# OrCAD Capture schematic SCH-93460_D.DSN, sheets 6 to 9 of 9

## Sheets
6 05. LED, MEMORY, XTAL: size C
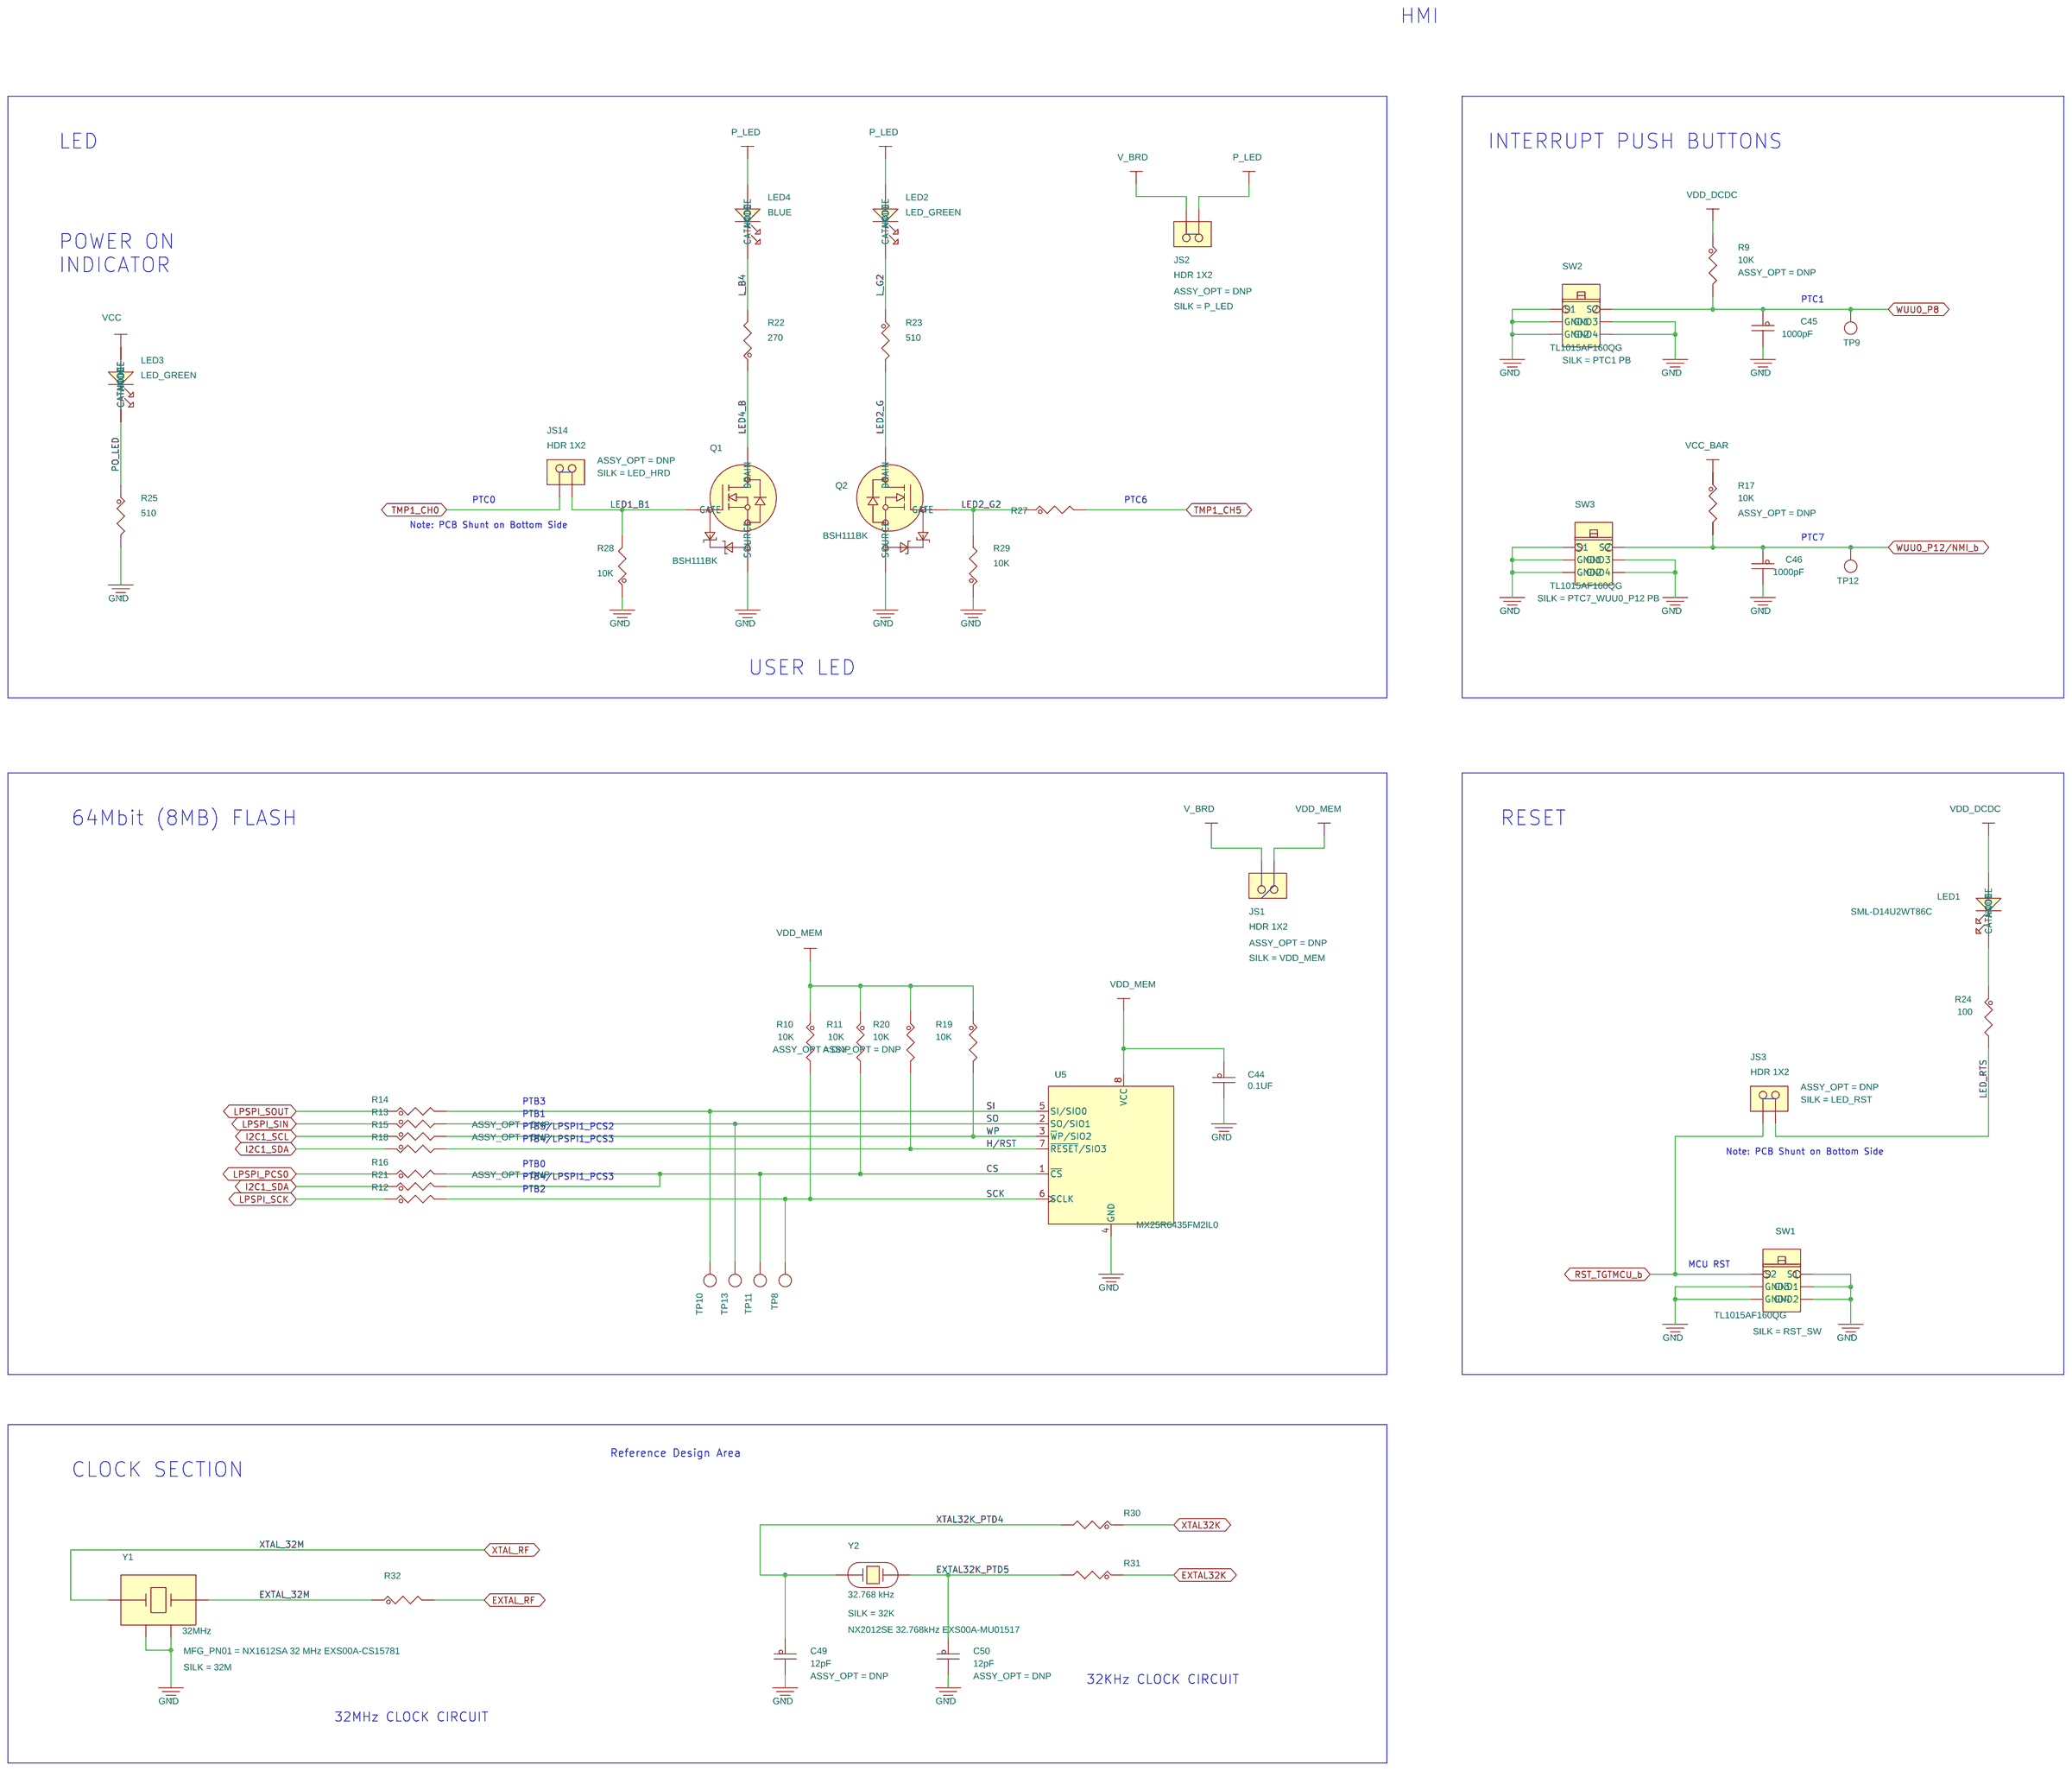
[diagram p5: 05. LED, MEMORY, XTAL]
7 06. MCU Link: size C
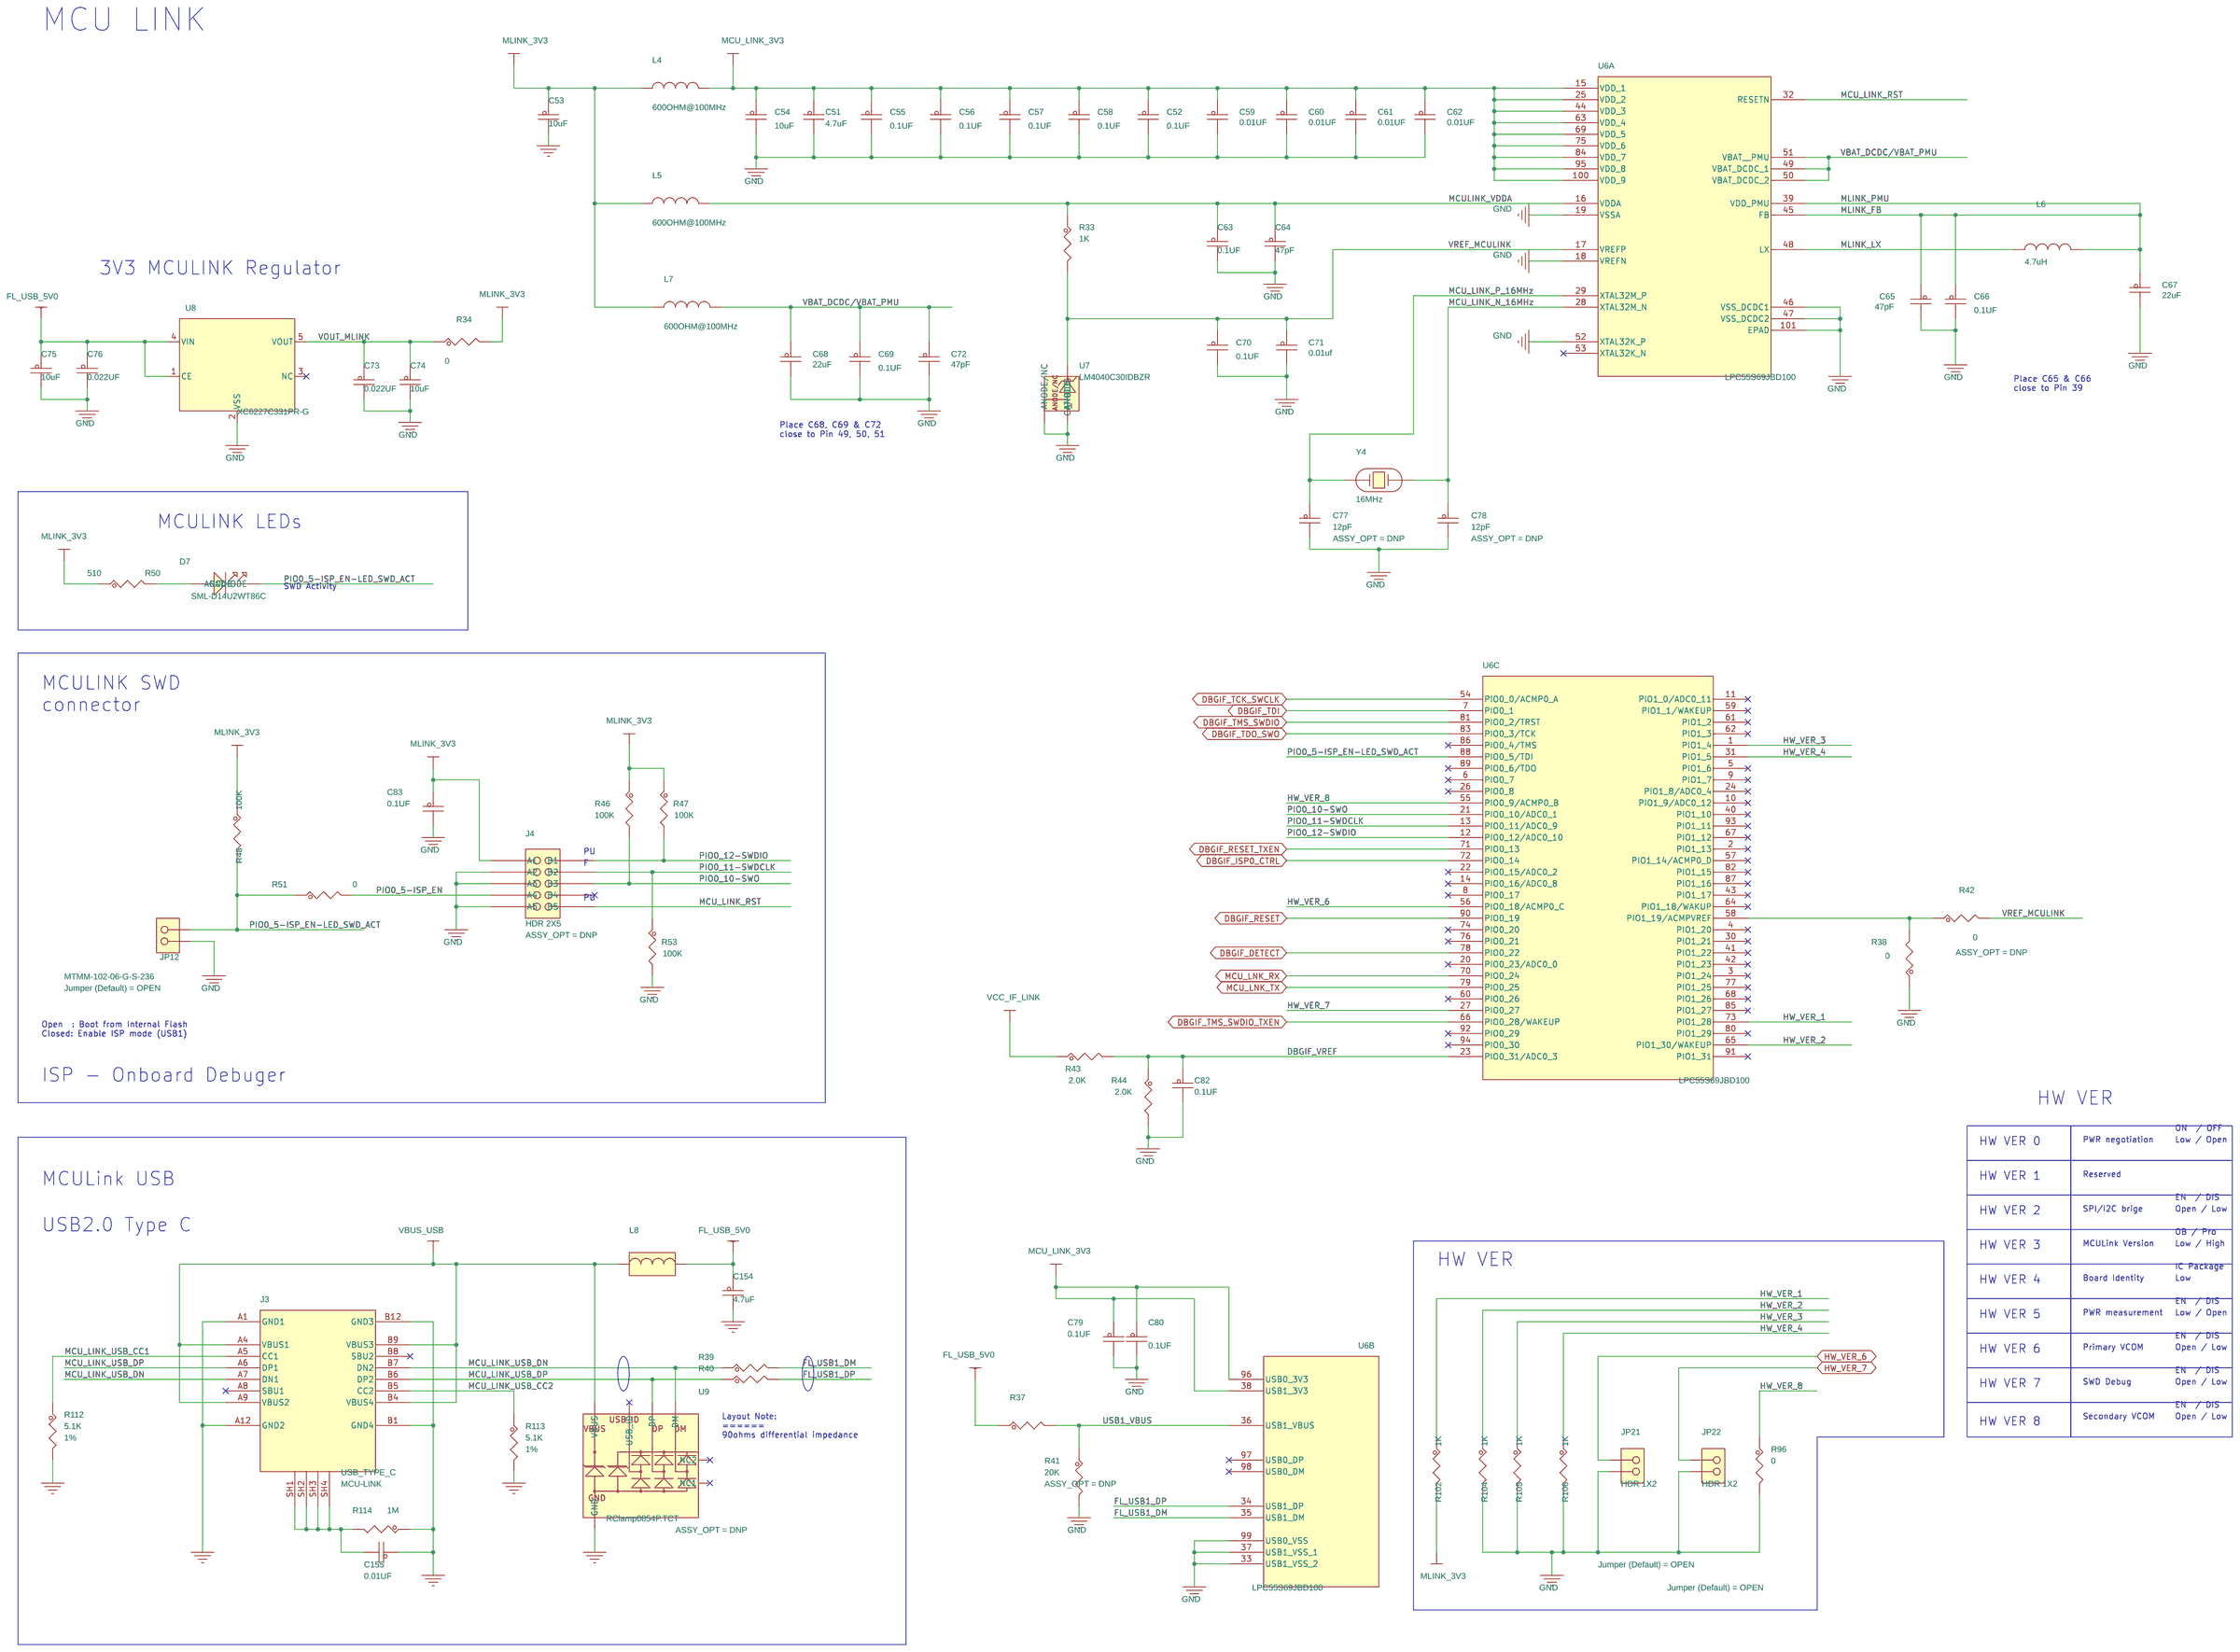
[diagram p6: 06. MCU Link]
8 07. MCU Link SWD: size C
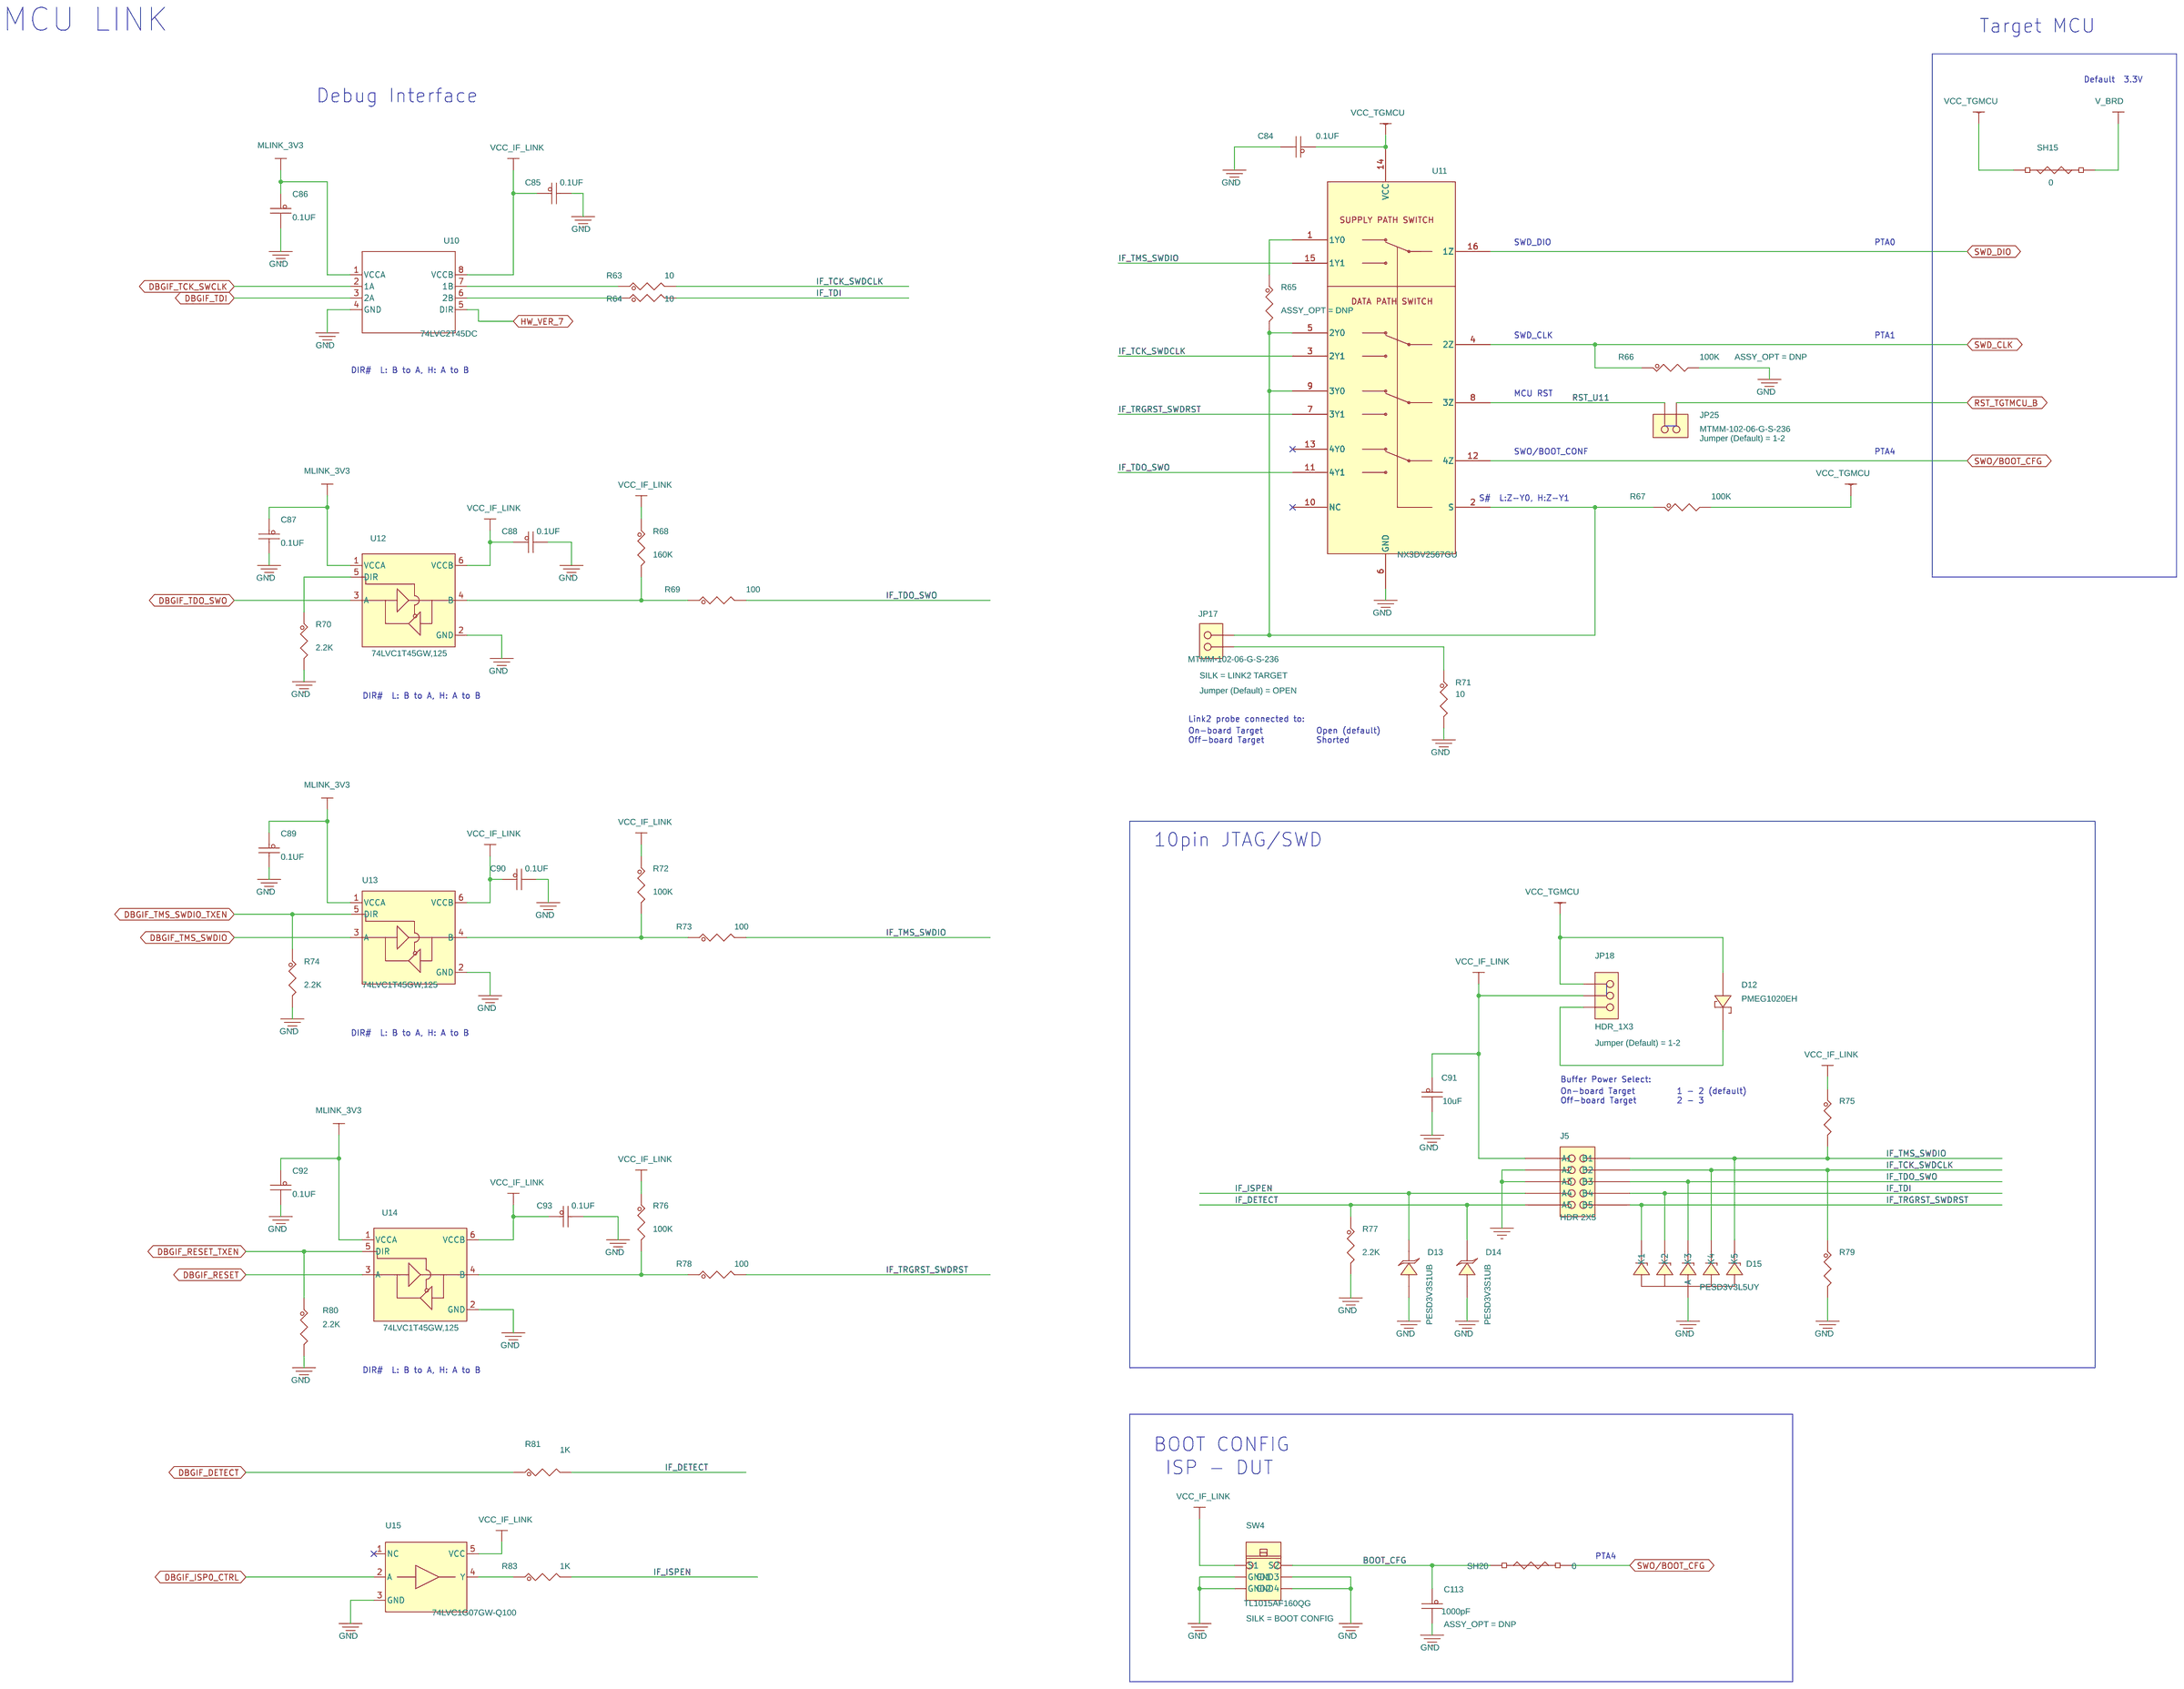
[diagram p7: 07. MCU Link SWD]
9 08. MLink IO, MikroBus: size C
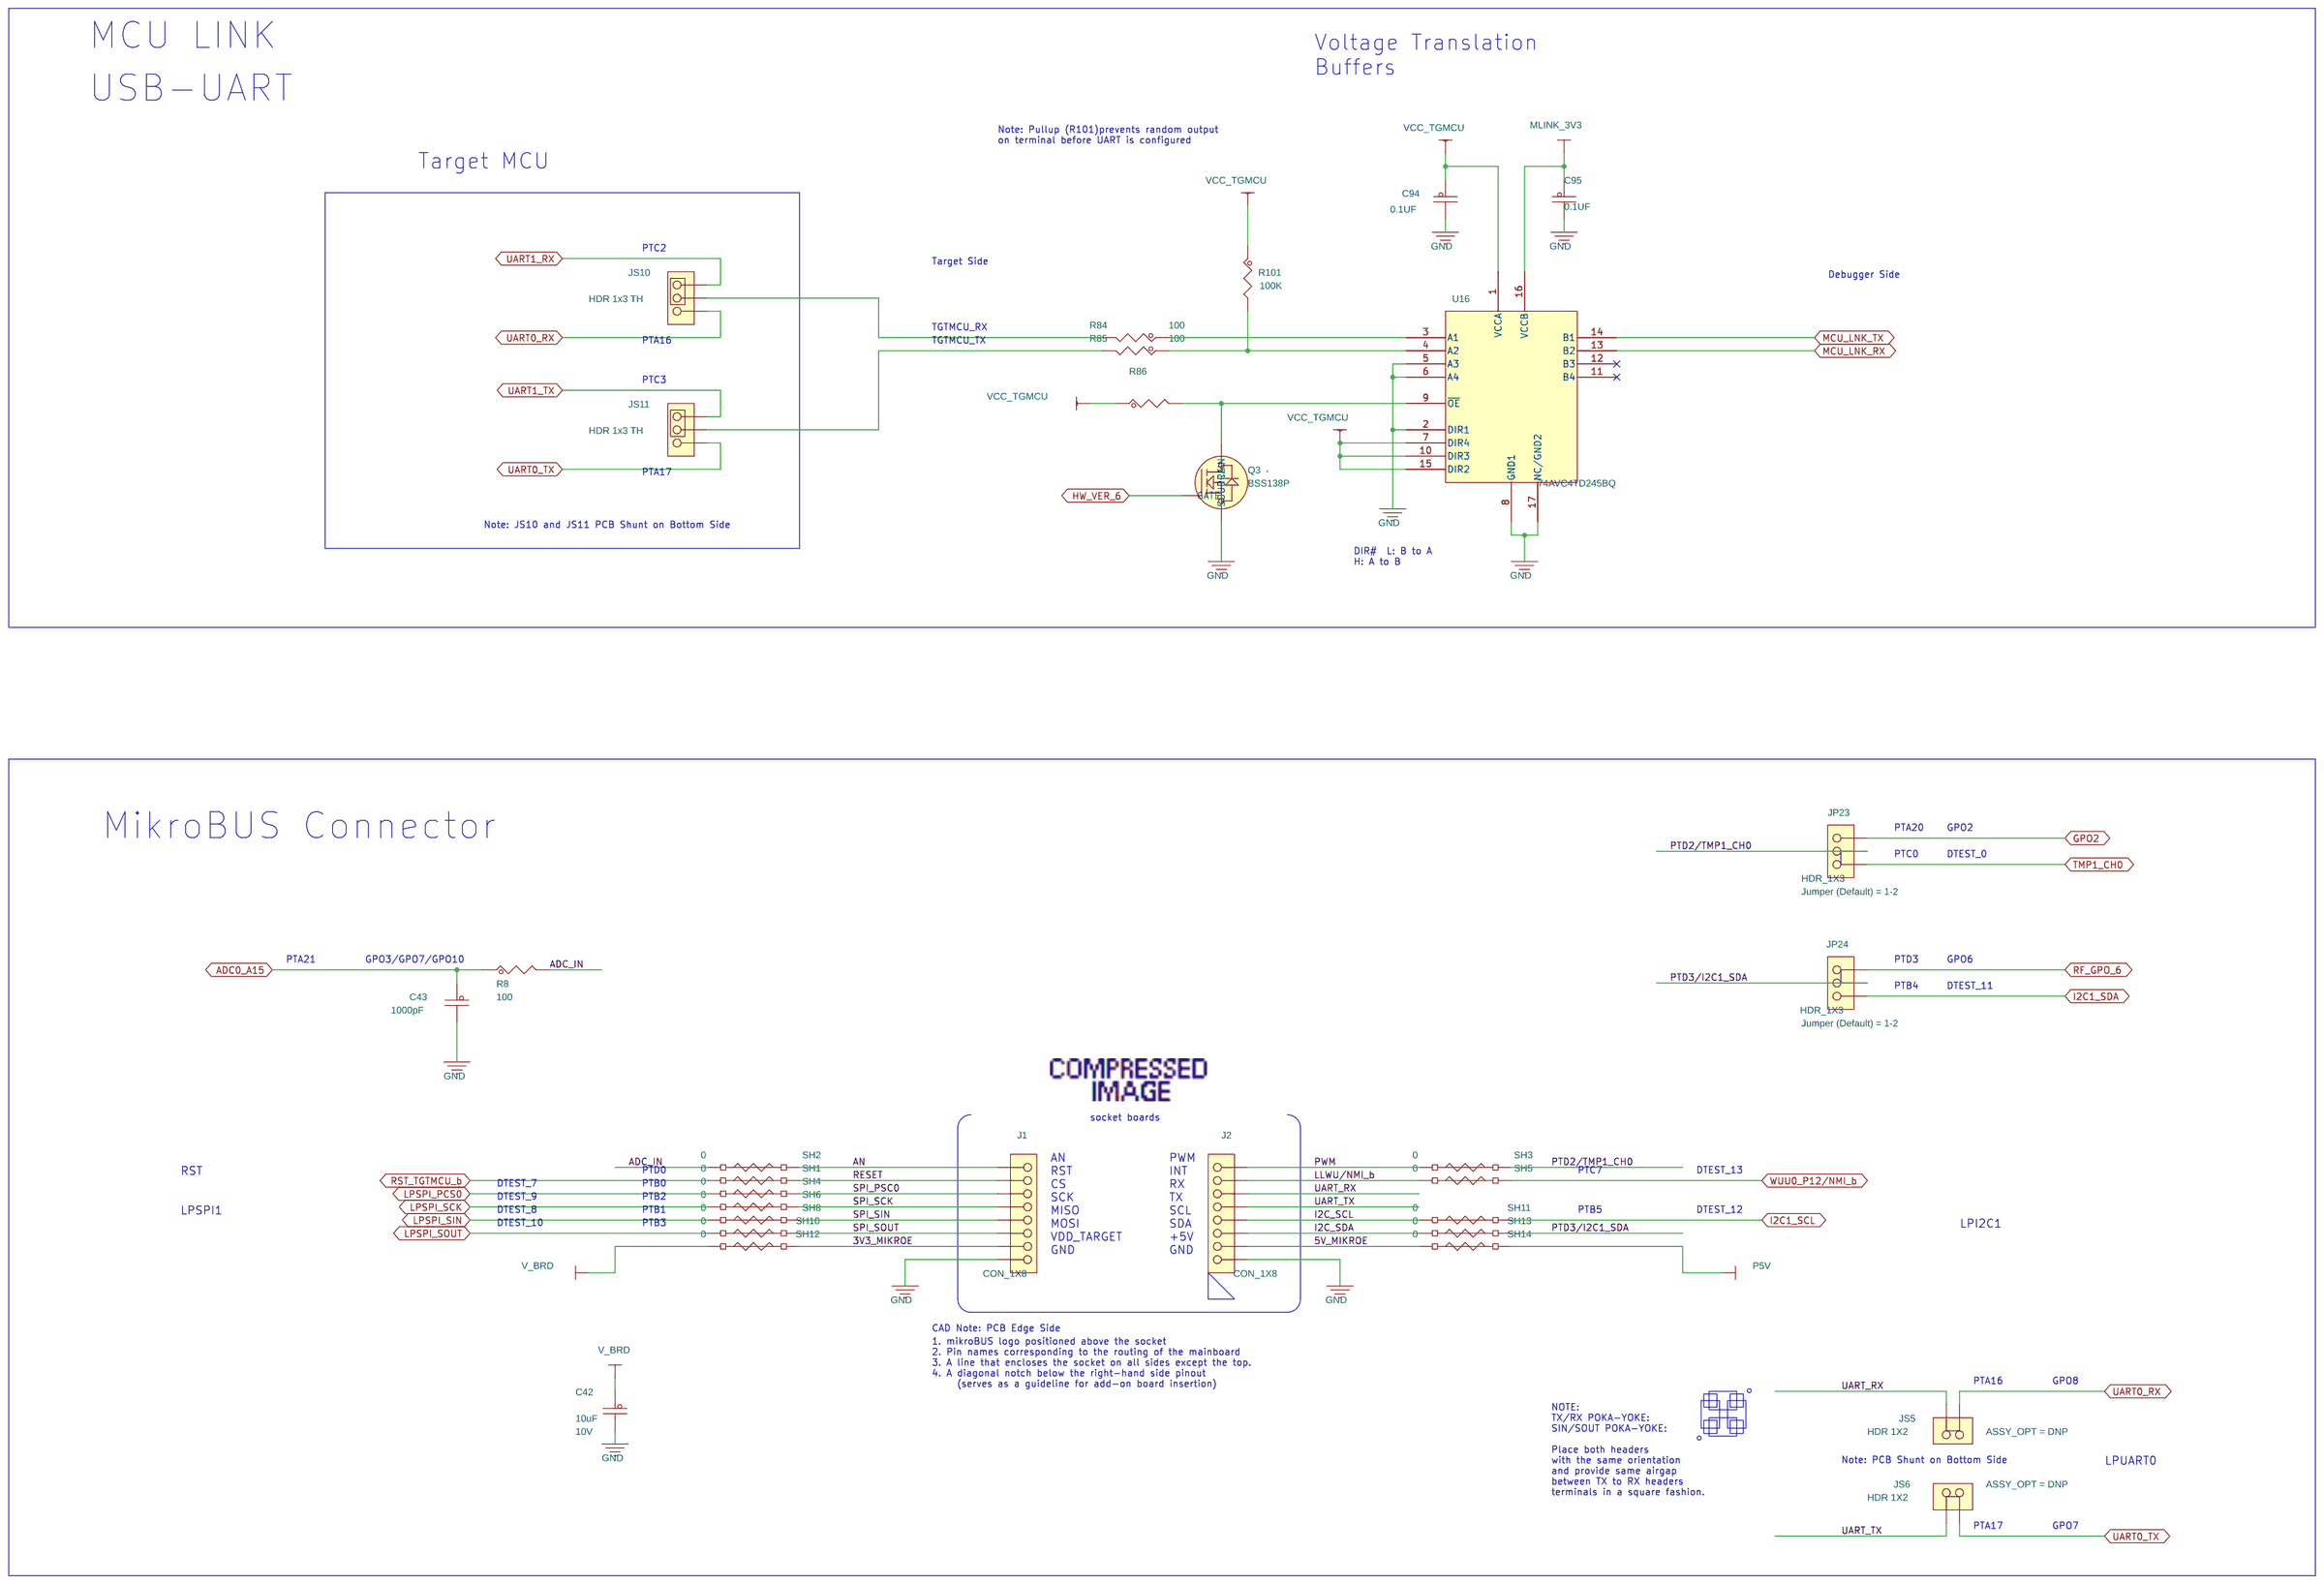
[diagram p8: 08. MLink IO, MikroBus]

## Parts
sheet 05. LED, MEMORY, XTAL
C44  0.1UF  [CC0402_25]
C45  1000pF  [CC0402_25]
C46  1000pF  [CC0402_25]
C49  12pF  [CC0402_25]
C50  12pF  [CC0402_25]
JS1  HDR 1X2  [sh_hdr102_2mm_bottom]
JS2  HDR 1X2  [sh_hdr102_2mm_bottom]
JS3  HDR 1X2  [sh_hdr102_2mm_bottom]
JS14  HDR 1X2  [sh_hdr102_2mm_bottom]
LED1  SML-D14U2WT86C  [led_0603]
LED2  LED_GREEN  [LED_0603]
LED3  LED_GREEN  [LED_0603]
LED4  BLUE  [led2_2p34_2p1x1p25]
Q1  BSH111BK  [SOT23_A]
Q2  BSH111BK  [SOT23_A]
R9  10K  [RC0402_25]
R10  10K  [RC0402_25]
R11  10K  [RC0402_25]
R12  0  [RC0402_25]
R13  0  [RC0402_25]
R14  0  [RC0402_25]
R15  0  [RC0402_25]
R16  0  [RC0402_25]
R17  10K  [RC0402_25]
R18  0  [RC0402_25]
R19  10K  [RC0402_25]
R20  10K  [RC0402_25]
R21  0  [RC0402_25]
R22  270  [RC0402_25]
R23  510  [RC0402_25]
R24  100  [RC0402_25]
R25  510  [RC0402_25]
R27  0  [RC0402_25]
R28  10K  [RC0402_25]
R29  10K  [RC0402_25]
R30  0  [RC0402_25]
R31  0  [RC0402_25]
R32  0  [RC0402_25]
SW1  TL1015AF160QG  [sw2_spst_4x3_sm]
SW2  TL1015AF160QG  [sw2_spst_4x3_sm]
SW3  TL1015AF160QG  [sw2_spst_4x3_sm]
TP8  TPAD_030  [TPAD_030]
TP9  TPAD_030  [TPAD_030]
TP10  TPAD_030  [TPAD_030]
TP11  TPAD_030  [TPAD_030]
TP12  TPAD_030  [TPAD_030]
TP13  TPAD_030  [TPAD_030]
U5  MX25R6435FM2IL0  [SO8_W]
Y1  32MHz  [xtal4_1p6x1p2]
Y2  32.768 kHz  [xtal2_2x1p2_sm]
sheet 06. MCU Link
C51  4.7uF  [CC0603_OV]
C52  0.1UF  [CC0402_25]
C53  10uF  [CC0805_OV]
C54  10uF  [CC0805_OV]
C55  0.1UF  [CC0402_25]
C56  0.1UF  [CC0402_25]
C57  0.1UF  [CC0402_25]
C58  0.1UF  [CC0402_25]
C59  0.01UF  [CC0402_25]
C60  0.01UF  [CC0402_25]
C61  0.01UF  [CC0402_25]
C62  0.01UF  [CC0402_25]
C63  0.1UF  [CC0402_25]
C64  47pF  [CC0603_OV]
C65  47pF  [CC0603_OV]
C66  0.1UF  [CC0402_25]
C67  22uF  [CC0603_OV]
C68  22uF  [CC0603_OV]
C69  0.1UF  [CC0402_25]
C70  0.1UF  [CC0402_25]
C71  0.01uf  [CC0603_OV]
C72  47pF  [CC0603_OV]
C73  0.022UF  [CC0603_OV]
C74  10uF  [CC0805_OV]
C75  10uF  [CC0805_OV]
C76  0.022UF  [CC0603_OV]
C77  12pF  [CC0402_25]
C78  12pF  [CC0402_25]
C79  0.1UF  [CC0402_25]
C80  0.1UF  [CC0402_25]
C82  0.1UF  [CC0402_25]
C83  0.1UF  [CC0402_25]
C154  4.7uF  [CC0603_OV]
C155  0.01UF  [CC0805_OV]
D7  SML-D14U2WT86C  [led_0603]
J3  USB_TYPE_C  [con16_usb_type-c_ra_th]
J4  HDR 2X5  [con2x5_50_th_a]
JP12  MTMM-102-06-G-S-236  [hdr102_tmm]
JP21  HDR 1X2  [hdr102_338h]
JP22  HDR 1X2  [hdr102_338h]
L4  600OHM@100MHz  [ind_1p8x1mm_sm]
L5  600OHM@100MHz  [ind_1p8x1mm_sm]
L6  4.7uH  [ind_5p2x5p2]
L7  600OHM@100MHz  [ind_1p8x1mm_sm]
L8  330 OHM  [ind_1608]
R33  1K  [RC0402_25]
R34  0  [RC0603_OV]
R37  10K  [RC0603_OV]
R38  0  [RC0603_OV]
R39  0  [RC0402_25]
R40  0  [RC0402_25]
R41  20K  [RC0402_25]
R42  0  [RC0603_OV]
R43  2.0K  [RC0603_OV]
R44  2.0K  [RC0603_OV]
R46  100K  [RC0402_25]
R47  100K  [RC0402_25]
R48  100K  [RC0402_25]
R50  510  [RC0402_25]
R51  0  [RC0603_OV]
R53  100K  [RC0402_25]
R96  0  [RC0603_OV]
R102  1K  [RC0402_25]
R104  1K  [RC0402_25]
R105  1K  [RC0402_25]
R106  1K  [RC0402_25]
R112  5.1K  [RC0402_25]
R113  5.1K  [RC0402_25]
R114  1M  [RC0805_OV]
U6  LPC55S69JBD100  [hlqfp100_0p5_14x14]  (sections A,B,C)
U7  LM4040C30IDBZR  [SOT23-3]
U8  XC6227C331PR-G  [SOT89-5]
U9  RClamp0854P.TCT  [slp1616p6]
Y4  16MHz  [xtal2_3p3x2p6]
sheet 07. MCU Link SWD
C84  0.1UF  [CC0402_25]
C85  0.1UF  [CC0402_25]
C86  0.1UF  [CC0402_25]
C87  0.1UF  [CC0402_25]
C88  0.1UF  [CC0402_25]
C89  0.1UF  [CC0402_25]
C90  0.1UF  [CC0402_25]
C91  10uF  [cc0402_tol0p2]
C92  0.1UF  [CC0402_25]
C93  0.1UF  [CC0402_25]
C113  1000pF  [CC0402_25]
D12  PMEG1020EH  [SOD123LF]
D13  PESD3V3S1UB  [sod523]
D14  PESD3V3S1UB  [sod523]
D15  PESD3V3L5UY  [sot-363_0p65_smt]
J5  HDR 2X5  [con2x5_50_th_a]
JP17  MTMM-102-06-G-S-236  [hdr102_tmm]
JP18  HDR_1X3  [hdr103_78mil]
JP25  MTMM-102-06-G-S-236  [hdr102_tmm]
R63  10  [RC0402_25]
R64  10  [RC0402_25]
R65  0  [RC0402_25]
R66  100K  [RC0402_25]
R67  100K  [RC0402_25]
R68  160K  [RC0402_25]
R69  100  [RC0402_25]
R70  2.2K  [RC0402_25]
R71  10  [RC0402_25]
R72  100K  [RC0402_25]
R73  100  [RC0402_25]
R74  2.2K  [RC0402_25]
R75  10K  [RC0402_25]
R76  100K  [RC0402_25]
R77  2.2K  [RC0402_25]
R78  100  [RC0402_25]
R79  10K  [RC0402_25]
R80  2.2K  [RC0402_25]
R81  1K  [RC0402_25]
R83  1K  [RC0402_25]
SH15  0  [SH0402]
SH20  0  [SH0603]
SW4  TL1015AF160QG  [sw2_spst_4x3_sm]
U10  74LVC2T45DC  [SSOP8_DCU]
U11  NX3DV2567GU  [pqfn16_0p4_2p65x1p85]
U12  74LVC1T45GW,125  [SOT-363_0P65_SMT]
U13  74LVC1T45GW,125  [SOT-363_0P65_SMT]
U14  74LVC1T45GW,125  [SOT-363_0P65_SMT]
U15  74LVC1G07GW-Q100  [sc70-5]
sheet 08. MLink IO, MikroBus
C42  10uF  [cc0402_tol0p2]
C43  1000pF  [CC0402_25]
C94  0.1UF  [CC0402_25]
C95  0.1UF  [CC0402_25]
J1  CON_1X8  [con_1x8_skt_2p54_th]
J2  CON_1X8  [con_1x8_skt_2p54_th]
JP23  HDR_1X3  [hdr103_78mil]
JP24  HDR_1X3  [hdr103_78mil]
JS5  HDR 1X2  [sh_hdr102_tmm_bottom]
JS6  HDR 1X2  [sh_hdr102_tmm_bottom]
JS10  HDR 1x3 TH  [hdr103_short1_2]
JS11  HDR 1x3 TH  [hdr103_short1_2]
Q3  BSS138P  [sot23_a]
R8  100  [RC0402_25]
R84  100  [RC0402_25]
R85  100  [RC0402_25]
R86  10K  [RC0402_25]
R101  100K  [RC0402_25]
SH1  0  [SH0402]
SH2  0  [SH0402]
SH3  0  [SH0402]
SH4  0  [SH0402]
SH5  0  [SH0402]
SH6  0  [SH0402]
SH8  0  [SH0402]
SH10  0  [SH0402]
SH11  0  [SH0402]
SH12  0  [SH0402]
SH13  0  [SH0402]
SH14  0  [SH0402]
U16  74AVC4TD245BQ  [dhvqfn16_0p5_3p6x2p6]

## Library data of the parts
C44 C52 C55-C58 C63 C66 C69 C70 C79 C80 C82 = CAP_NP: CAP CER 0.1UF 16V 10% X7R 0402; 3D_Mechanical_Footprint_File: http://fcl.am.freescale.net/ALLEGRO/step/cc0402_25.STEP; AGILE_PN: 150-75182; CAD_APPROVED: Yes; FPLIST: CC0402_25,CC0402_HD,0402_CC,CAPC0402_L; HEIGHT: 0.635mm; MFG_NAME01: KEMET; MFG_PN01: C0402C104K4RACTU; ROHS: NULL; Rated Voltage: 16V; Temp Range: -55C to +125C; Tolerance: 10%; VOLTAGE: 16V
C43 C45 C46 = CAP_NP: CAP CER 1000PF 50V 5% C0G 0402; AGILE_PN: 150-76334; CAD_APPROVED: Yes; FPLIST: CC0402_25,CC0402_HD,0402_CC; HEIGHT: 0.55mm; MFG_NAME01: GUANGDONG VIIYONG ELECTRONIC TECHNOLOGYCO., LTD.VIIYONG; MFG_PN01: V102J0402C0G500NBT; Package Size: 0402; Package Type: 180mm Paper Tape; ROHS: NULL; Rated Voltage: 50V; Temp Range: -55C to +125C; Tolerance: 5%; VOLTAGE: 50V
C49 C50 C77 C78 = CAP_NP: CAP CER 12pF 50V 5% C0G AEC-Q200 0402; AGILE_PN: 150-80457; ASSY_OPT: DNP; CAD_APPROVED: Yes; FPLIST: CC0402_25,CC0402_HD,0402_CC,capc0402_l; HEIGHT: 0.55MM; MFG_NAME01: MURATA; MFG_PN01: GCM1555C1H120JA16D; Package Size: 0402; ROHS: NULL; Rated Voltage: 50V; Temp Range: -55C to +125C; Tolerance: 5%; VOLTAGE: 50V
JS1 = CONN_HDR_2X1: HDR 1X2 TH 2MM SP 217H AU 110L, NO PART TO ORDER; AGILE_PN: 210-80699; ASSY_OPT: DNP; CAD_APPROVED: Yes; FPLIST: sh_hdr102_2mm_bottom,sh_hdr102_2mm_bottom_a; HEIGHT: 5.2; MFG_PN01: NO_PART_TO_ORDER; ROHS: Yes; SHORTED (DEFAULT): CLOSED; SILK: VDD_MEM; Temp_Range: -55°C to +125°C
JS2 = CONN_HDR_2X1: HDR 1X2 TH 2MM SP 217H AU 110L, NO PART TO ORDER; AGILE_PN: 210-80699; ASSY_OPT: DNP; CAD_APPROVED: Yes; FPLIST: sh_hdr102_2mm_bottom,sh_hdr102_2mm_bottom_a; HEIGHT: 5.2; MFG_PN01: NO_PART_TO_ORDER; ROHS: Yes; SHORTED (DEFAULT): CLOSED; SILK: P_LED; Temp_Range: -55°C to +125°C
JS3 = CONN_HDR_2X1: HDR 1X2 TH 2MM SP 217H AU 110L, NO PART TO ORDER; AGILE_PN: 210-80699; ASSY_OPT: DNP; CAD_APPROVED: Yes; FPLIST: sh_hdr102_2mm_bottom,sh_hdr102_2mm_bottom_a; HEIGHT: 5.2; MFG_PN01: NO_PART_TO_ORDER; ROHS: Yes; SHORTED (DEFAULT): CLOSED; SILK: LED_RST; Temp_Range: -55°C to +125°C
JS14 = CONN_HDR_2X1: HDR 1X2 TH 2MM SP 217H AU 110L, NO PART TO ORDER; AGILE_PN: 210-80699; ASSY_OPT: DNP; CAD_APPROVED: Yes; FPLIST: sh_hdr102_2mm_bottom,sh_hdr102_2mm_bottom_a; HEIGHT: 5.2; MFG_PN01: NO_PART_TO_ORDER; ROHS: Yes; SHORTED (DEFAULT): CLOSED; SILK: LED_HRD; Temp_Range: -55°C to +125°C
D7 LED1 = LED: LED RED SGL 20mA 2V AEC-Q101 0603; AGILE_PN: 370-76847; CAD_APPROVED: Yes; HEIGHT: 0.55; MFG_NAME01: ROHM; Package Size: 0603 (1608 Metric); Rated Voltage: 2V; Temp Range: -40C to +100C; VOLTAGE: 2V
LED2 LED3 = LED: LED ULTRA-BRIGHT GREEN SMT 0603; AGILE_PN: 370-75077; CAD_APPROVED: YES; HEIGHT: 0.8; MFG_NAME01: LITE ON; MFG_PN01: LTST-C190KGKT; ROHS: Yes; Rated Voltage: 2V; VOLTAGE: 2V
LED4 = LED: LED BLUE SGL 20MA SMT 0805; 3D_Mechanical_Footprint_File: http://fcl.am.freescale.net/ALLEGRO/step/led2_2p34_2p1x1p25.step; AGILE_PN: 370-76451; CAD_APPROVED: Yes; HEIGHT: 0.9; MFG_NAME01: LITE ON; MFG_PN01: LTST-C171TBKT; Rated Voltage: 2.8V; Temp Range: -20° C to +80° C; VOLTAGE: 2.8V
Q1 Q2 = NMOS_2N7002BKW_3P: TRAN NMOS SW FET 55V 210mA SOT23; AGILE_PN: 480-79704; CAD_APPROVED: Yes; HEIGHT: 1.1; MFG_NAME01: NEXPERIA; MFG_PN01: BSH111BKR; ROHS: Yes
R9 R11 R17 = RES: RES MF 10K 1/16W 1% 0402; AGILE_PN: 470-80452; ASSY_OPT: DNP; CAD_APPROVED: Yes; FPLIST: RC0402_25,RC0402_HD,0402_CC; HEIGHT: 0.40; MFG_NAME01: VISHAY; MFG_PN01: CRCW040210K0FKEDC; PRIORITY_PN: 006-00552; ROHS: Yes; TOL: 1%; Tolerance: 1%
R10 = RES: RES MF 10K 1/16W 1% 0402; AGILE_PN: 470-80452; ASSY_OPT: DNP; CAD_APPROVED: Yes; FPLIST: RC0402_25,RC0402_HD,0402_CC; HEIGHT: 0.40; MFG_NAME01: VISHAY; MFG_PN01: CRCW040210K0FKEDC; ROHS: Yes; Tolerance: 1%
R12-R14 R16 R27 R30-R32 R39 R40 = RES: RES MF ZERO OHM 1/16W 5% 0402; AGILE_PN: 470-75394; CAD_APPROVED: Yes; FPLIST: RC0402_25,RC0402_HD,RC0402_X2,0402_CC; HEIGHT: 0.45; MFG_NAME01: YAGEO AMERICA; MFG_PN01: RC0402JR-070RL; ROHS: Yes; Temp Range: -55 to +155C; Tolerance: 5%; VOLTAGE: 1/16W
R15 R18 R21 R65 = RES: RES MF ZERO OHM 1/16W 5% 0402; AGILE_PN: 470-75394; ASSY_OPT: DNP; CAD_APPROVED: Yes; FPLIST: RC0402_25,RC0402_HD,RC0402_X2,0402_CC; HEIGHT: 0.45; MFG_NAME01: YAGEO AMERICA; MFG_PN01: RC0402JR-070RL; ROHS: Yes; Temp Range: -55 to +155C; Tolerance: 5%; VOLTAGE: 1/16W
R19 R20 R28 R29 = RES: RES MF 10K 1/16W 1% 0402; AGILE_PN: 470-80452; CAD_APPROVED: Yes; FPLIST: RC0402_25,RC0402_HD,0402_CC; HEIGHT: 0.40; MFG_NAME01: VISHAY; MFG_PN01: CRCW040210K0FKEDC; ROHS: Yes; Tolerance: 1%
R22 = RES: RES MF 270 OHM 1/16W 1% AEC-Q200 0402; 3D_Mechanical_Footprint_File: http://fcl.am.freescale.net/ALLEGRO/step/rc0402_25.STEP; AGILE_PN: 470-83516; CAD_APPROVED: Yes; FPLIST: RC0402_25,RC0402_HD,0402_CC; HEIGHT: 0.37; MFG_NAME01: YAGEO AMERICA; MFG_PN01: AC0402FR-07270RL; Package Size: 0402 (1005 Metric); ROHS: Yes; Temp Range: -55C to +155C; Tolerance: 1%
R23 R25 = RES: RES 510 OHMS 1/16W 5% RC0402 ROHS; AGILE_PN: 470-76237; CAD_APPROVED: Yes; FPLIST: RC0402_25,RC0402_HD,0402_CC; HEIGHT: 0.4; MFG_NAME01: YAGEO AMERICA; MFG_PN01: RC0402JR-07510RL; ROHS: Yes
R8 R24 R69 R73 R78 R84 R85 = RES: RES MF 100 OHM 1/16W 5% 0402; AGILE_PN: 470-75591; CAD_APPROVED: Yes; FPLIST: RC0402_25,RC0402_HD,RC0402_X2,0402_CC; HEIGHT: 0.45; MFG_NAME01: BOURNS; MFG_PN01: CR0402-JW-101GLF; ROHS: Yes; Tolerance: 5%
SW1 = SW_SPNO_2P_GND6P: SW SPST PB 50MA 12V SMT; AGILE_PN: 510-77720; CAD_APPROVED: Yes; HEIGHT: 2.4; MFG_NAME01: E SWITCH; ROHS: Yes; SILK: RST_SW
SW2 = SW_SPNO_2P_GND6P: SW SPST PB 50MA 12V SMT; AGILE_PN: 510-77720; CAD_APPROVED: Yes; HEIGHT: 2.4; MFG_NAME01: E SWITCH; ROHS: Yes; SILK: PTC1 PB
SW3 = SW_SPNO_2P_GND6P: SW SPST PB 50MA 12V SMT; AGILE_PN: 510-77720; CAD_APPROVED: Yes; HEIGHT: 2.4; MFG_NAME01: E SWITCH; ROHS: Yes; SILK: PTC7_WUU0_P12 PB
TP8-TP13 = TESTLOOP: TEST POINT PAD 30MIL DIA SMT, NO PART TO ORDER; 3D_Mechanical_Footprint_File: http://fcl.am.freescale.net/ALLEGRO/step/tpad_030.STEP; AGILE_PN: 211-76642; CAD_APPROVED: Yes; HEIGHT: 0.1; MFG_NAME01: NOTACOMPONENT; MFG_PN01: NOTACOMPONENT; ROHS: Yes
U5 = MX25R6435FM2IL0: IC MEM FLASH NOR 64Mb SPI SERIAL 1.65-3.6V SOP8; AGILE_PN: 342-00647; CAD_APPROVED: Yes; HEIGHT: 2.16; MFG_NAME01: MACRONIX INTERNATIONAL CO., LTD; ROHS: Yes; VOLTAGE: 1.65-3.6V
Y1 = XTAL_13: XTAL 32MHz 6pF AEC-Q200 SMT; 3D_Mechanical_Footprint_File: http://fcl.am.freescale.net/ALLEGRO/step/xtal4_1p6x1p2.STEP; AGILE_PN: 230-10023; CAD_APPROVED: Yes; HEIGHT: 0.35mm; MFG_NAME01: NDK; MFG_PN01: NX1612SA 32 MHz EXS00A-CS15781; Package Size: 1.6 x 1.2 x 0.3 mm; ROHS: Yes; SILK: 32M; Temp Range: -40°C to 125°C
Y2 = XTAL: XTAL 32.768KHz FIXED 12.5pF -- AEC-Q200 SMT; 3D_Mechanical_Footprint_File: http://fcl.am.freescale.net/ALLEGRO/xtal2_2x1p2_sm.STEP; AGILE_PN: 230-78455; CAD_APPROVED: YES; Frequency Tolerance: +/- 20 PPM; HEIGHT: 0.6MM; MFG_NAME01: NDK; MFG_PN01: NX2012SE 32.768kHz EXS00A-MU01517; ROHS: NULL; SILK: 32K; Temp Range: -40 C TO -125 C
C51 = CAP_NP: CAP CER 4.7uF 25V 10% X6S AEC-Q200 0603; AGILE_PN: 150-79698; CAD_APPROVED: Yes; FPLIST: CC0603_OV,CC0603; HEIGHT: 1; MFG_NAME01: MURATA; MFG_PN01: GRT188C81E475KE13; Package Size: 0603; ROHS: Yes; Rated Voltage: 25V; Temp Range: -55C to +105C; Tolerance: 10%; VOLTAGE: 25V
C53 C54 C74 C75 = CAP_NP: CAP CER 10uF 16V 20% X7S AEC-Q200 0805; AGILE_PN: 150-79516; CAD_APPROVED: Yes; FPLIST: CC0805_OV,CC0805,0805_CC; HEIGHT: 1.45; MFG_NAME01: TDK; MFG_PN01: CGA4J1X7S1C106M125AC; ROHS: Yes; Rated Voltage: 16V; Temp Range: -55C to +125C; Tolerance: 20%; VOLTAGE: 16V
C59-C62 = CAP_NP: CAP CER 0.01UF 25V 10% X8R 0402; AGILE_PN: 150-77996; CAD_APPROVED: Yes; FPLIST: CC0402_25,CC0402_HD,0402_CC; HEIGHT: 0.55; MFG_NAME01: TDK; MFG_PN01: C1005X8R1E103K050BA; ROHS: Yes; Rated Voltage: 25V; Temp Range: -55C to +150C; Tolerance: 10%; VOLTAGE: 25V
C64 C65 C72 = CAP_NP: CAP CER 47pF 50V 5% C0G AEC-Q200 0603; AGILE_PN: 150-79357; CAD_APPROVED: Yes; FPLIST: CC0603_OV,CC0603,0603_CC; HEIGHT: 0.9; MFG_NAME01: TDK; MFG_PN01: CGA3E2C0G1H470J080AA; Package Size: 0603; Package Type: Reel; ROHS: Yes; Rated Voltage: 50V; Temp Range: -55C to +125C; Tolerance: 5%; VOLTAGE: 50V
C67 C68 = CAP_NP: CAP CER 22uF 10V 20% X5R 0603; 3D_Mechanical_Footprint_File: http://fcl.am.freescale.net/ALLEGRO/step/cc0603_ov.STEP; AGILE_PN: 150-79530; CAD_APPROVED: Yes; FPLIST: CC0603_OV,CC0603; HEIGHT: 1.05mm; MFG_NAME01: SAMSUNG; MFG_PN01: CL10A226MP7LUNC; Package Size: 0603 [1608 Metric]; Package Type: SMD/SMT; ROHS: NULL; Rated Voltage: 10V; Temp Range: -55°C to 85°C; Tolerance: 20%; VOLTAGE: 10V
C71 = CAP_NP: CAP CER 0.01uF 50V 10% X7R AEC-Q200 0603; AGILE_PN: 150-79361; CAD_APPROVED: Yes; FPLIST: CC0603_OV,CC0603,0603_CC; HEIGHT: 0.9; MFG_NAME01: TDK; MFG_PN01: CGA3E2X7R1H103K080AA; Package Size: 0603; Package Type: 7; ROHS: Yes; Rated Voltage: 50V; Temp Range: -55C to +125C; Tolerance: 10%; VOLTAGE: 50V
C73 C76 = CAP_NP: CAP CER 0.022UF 50V 20% X7R 0603; AGILE_PN: 150-30153; CAD_APPROVED: Yes; FPLIST: CC0603_OV,CC0603,0603_CC; HEIGHT: 0.86; MFG_NAME01: AVX; MFG_PN01: 06035C223MAT2A; Package Size: 0603; ROHS: Yes; Rated Voltage: 50V; Temp Range: -55C to +125C; Tolerance: 20%; VOLTAGE: 50V
C83 = CAP_NP: CAP CER 0.1UF 16V 10% X7R 0402; 3D_Mechanical_Footprint_File: http://fcl.am.freescale.net/ALLEGRO/step/cc0402_25.STEP; AGILE_PN: 150-75182; CAD_APPROVED: Yes; FPLIST: CC0402_25,CC0402_HD,0402_CC,CAPC0402_L; HEIGHT: 0.635mm; MFG_NAME01: KEMET; MFG_PN01: C0402C104K4RACTU; ROHS: NULL; Rated Voltage: 16V; Temp Range: -55C to +125C; Temp_Range: -55°C to +125°C; Tolerance: 10%; VOLTAGE: 16V
C154 = CAP_NP: CAP CER 4.7uF 10V 20% X5R 0603; 3D_Mechanical_Footprint_File: http://fcl.am.freescale.net/ALLEGRO/step/cc0603_ov.STEP; AGILE_PN: 150-81893; CAD_APPROVED: Yes; FPLIST: CC0603_OV,CC0603,0603_CC; HEIGHT: 0.87; MFG_NAME01: WURTH ELEKTRONIK; MFG_PN01: 885012106012; Package Size: 0603; Package Type: WCAP-CSGP_0603; ROHS: Yes; Rated Voltage: 10V; TOL: 20%; Temp Range: -55C TO 85C; Tolerance: 20%; VOLTAGE: 10V
C155 = CAP_NP: CAP CER 0.01UF 50V 10% X7R 0805; AGILE_PN: 150-75010; CAD_APPROVED: Yes; FPLIST: CC0805_OV,CC0805,0805_CC; HEIGHT: 1.4732; MFG_NAME01: VENKEL COMPANY; MFG_PN01: C0805X7R500-103KNE; Package Size: 0805; ROHS: Yes; Rated Voltage: 50V; Temp Range: -55C to +125C; Tolerance: 10%
J3 = USB16_TYPEC_4SH: CON 2X8 USB2.0_TYPE_C RCPT 0.85MM 144H AU 63L; 3D_Mechanical_Footprint_File: http://fcl.am.freescale.net/ALLEGRO/step/con16_usb_type-c_ra_th.STEP; AGILE_PN: 210-82931; CAD_APPROVED: Yes; HEIGHT: 3.66; MFG_NAME01: GCT; MFG_PN01: USB4085-GF-A; Package Type: Through Hole, Right Angle; ROHS: Yes; SILK: MCU-LINK; Temp Range: -40 °C to +85 °C
J4 = CONN_HDR_5X2: HDR 2X5 TH 50MIL CTR 222H AU 90L; 3D_Mechanical_Footprint_File: http://fcl.am.freescale.net/ALLEGRO/step/con2x5_50_th_a.STEP; AGILE_PN: 210-82391; ASSY_OPT: DNP; CAD_APPROVED: Yes; HEIGHT: 5.65; MFG_NAME01: WURTH ELEKTRONIK EISOS GMBH & CO. KG (ELECTRONIC & ELECTROMEHANICAL COMP); MFG_PN01: 62201021121; ROHS: Yes; Temp Range: -40C to +105C; Temp_Range: -55DegC to +105DegC
JP12 = CONN_HDR_2X1: HDR 1X2 TH 2MM SP 300H AU 102L; AGILE_PN: 210-80456; CAD_APPROVED: Yes; HEIGHT: 7.62; Jumper (Default): OPEN; MFG_NAME01: SAMTEC; ROHS: Yes
JP21 JP22 = CONN_HDR_2X1: HDR 1X2 TH 100MIL SP 338H SN 100L; 3D_Mechanical_Footprint_File: http://fcl.am.freescale.net/ALLEGRO/step/hdr102_338h.STEP; AGILE_PN: 210-80102; CAD_APPROVED: Yes; HEIGHT: 8.58; Jumper (Default): OPEN; MFG_NAME01: SAMTEC; MFG_PN01: TSW-102-07-T-S; Package Size: 5.08 x 2.54 mm; ROHS: Yes; Temp Range: -55°C to +125°C
L4 L5 L7 = INDUCTOR: IND FER BEAD 600OHM@100MHz 1A 25% 0603; 3D_Mechanical_Footprint_File: http://fcl.am.freescale.net/ALLEGRO/step/ind_1p8x1mm_sm.step; AGILE_PN: 180-78469; CAD_APPROVED: Yes; HEIGHT: 1mm; MFG_NAME01: WURTH ELEKTRONIK EISOS GMBH & CO. KG (ELECTRONIC & ELECTROMEHANICAL COMP); MFG_PN01: 742792651; ROHS: NULL; Temp Range: -55° C to +125° C
L6 = INDUCTOR: IND WW PWR 4.7UH@40MHZ 3A 30% SMT; 3D_Mechanical_Footprint_File: http://fcl.am.freescale.net/ALLEGRO/step/ind_5p2x5p2.STEP; AGILE_PN: 180-78209; CAD_APPROVED: Yes; HEIGHT: 2.2; MFG_NAME01: MURATA; MFG_PN01: LQH5BPN4R7NT0; ROHS: Yes
L8 = BEAD: IND FER BEAD 330OHM@100MHZ 1.7A 0603; AGILE_PN: 180-78156; CAD_APPROVED: Yes; HEIGHT: 0.95; MFG_NAME01: TDK; MFG_PN01: MPZ1608S331A; PART_TYPE: FERRITE\BEAD; ROHS: Yes; TOL: 25%; Tolerance: 25%
R33 R81 R83 R102 R104-R106 = RES: RES MF 1K 1/16W 0.5% 0402; AGILE_PN: 470-80057; CAD_APPROVED: Yes; FPLIST: RC0402_25,RC0402_HD,0402_CC; HEIGHT: 0.4; MFG_NAME01: PANASONIC; MFG_PN01: ERA2AED102X; ROHS: Yes; Tolerance: 0.5%
R34 R38 R51 R96 = RES: RES MF ZERO OHM 1/10W -- 0603; AGILE_PN: 470-80866; CAD_APPROVED: Yes; FPLIST: RC0603_OV,RC0603,R603-X2,0603_CC; HEIGHT: 0.6; MFG_NAME01: YAGEO AMERICA; MFG_PN01: RC0603FR-070RL; ROHS: NULL; Temp Range: –55 °C to +155 °C
R37 = RES: RES MF 10K 1/10W 5% 0603; AGILE_PN: 470-75410; CAD_APPROVED: Yes; FPLIST: RC0603_OV,RC0603,0603_CC; HEIGHT: 0.55; MFG_NAME01: BOURNS; MFG_PN01: CR0603-JW-103ELF; ROHS: Yes; Temp Range: –55 °C to +155 °C; Tolerance: 5%
R41 = RES: RES MF 20K 1/10W 0.1% AEC-Q200 0402; AGILE_PN: 470-82089; ASSY_OPT: DNP; CAD_APPROVED: Yes; FPLIST: RC0402_25,RC0402_HD,0402_CC; HEIGHT: 0.4; MFG_NAME01: VISHAY INTERTECHNOLOGY; MFG_PN01: MCS0402MD2002BE100; ROHS: Yes; Temp Range: -55°C ~ 125°C; Tolerance: 0.1%; VOLTAGE: 50V
R42 = RES: RES MF ZERO OHM 1/10W -- 0603; AGILE_PN: 470-80866; ASSY_OPT: DNP; CAD_APPROVED: Yes; FPLIST: RC0603_OV,RC0603,R603-X2,0603_CC; HEIGHT: 0.6; MFG_NAME01: YAGEO AMERICA; MFG_PN01: RC0603FR-070RL; ROHS: NULL; Temp Range: –55 °C to +155 °C
R43 R44 = RES: RES MF 2.0K 1/10W 5% 0603; AGILE_PN: 470-75408; CAD_APPROVED: Yes; FPLIST: RC0603_OV,RC0603,0603_CC; HEIGHT: 0.55; MFG_NAME01: BOURNS; MFG_PN01: CR0603-JW-202ELF; ROHS: Yes; Tolerance: 5%; VOLTAGE: 1/10W
R46-R48 R53 R67 R72 R76 R101 = RES: RES MF 100K 1/16W 1% 0402; AGILE_PN: 470-76240; CAD_APPROVED: Yes; FPLIST: RC0402_25,RC0402_HD,0402_CC; HEIGHT: 0.4; MFG_NAME01: VISHAY INTERTECHNOLOGY; MFG_PN01: CRCW0402100KFKEDC; ROHS: Yes; Tolerance: 1%
R50 = RES: RES 510 OHMS 1/16W 5% RC0402 ROHS; AGILE_PN: 470-76237; CAD_APPROVED: Yes; FPLIST: RC0402_25,RC0402_HD,0402_CC; HEIGHT: 0.4; MFG_NAME01: YAGEO AMERICA; MFG_PN01: RC0402JR-07510RL; ROHS: Yes; Temp_Range: -55C to +155C
R112 R113 = RES: RES MF 5.1K 1/16W 1% 0402; AGILE_PN: 470-76474; CAD_APPROVED: Yes; FPLIST: RC0402_25,RC0402_HD,0402_CC; HEIGHT: 0.4; MFG_NAME01: THYE MING TECH CO LTD; MFG_PN01: CR02FL6--5K1; ROHS: Yes; Tolerance: 1%
R114 = RES: RES MF 1M 1/10W 5%  0805; AGILE_PN: 470-76691; CAD_APPROVED: Yes; FPLIST: RC0805_OV,RC0805,0805_CC; HEIGHT: 0.55; MFG_NAME01: SMEC; MFG_PN01: RC73L2A105JTF; ROHS: Yes; Temp Range: -55°C to +175°C; Tolerance: 5%
U6 = LPC55S69JB_HLQFP100: IC MCU 32BIT ARM FLASH 640KB SRAM 320KB 1.8-3.6V HLQFP100; 3D_Mechanical_Footprint_File: http://fcl.am.freescale.net/ALLEGRO/step/hlqfp100_0p5_14x14.step; AGILE_PN: 344-02385; CAD_APPROVED: Yes; HEIGHT: 1.6; MFG_NAME01: NXP SEMICONDUCTOR; ROHS: Yes; Temp Range: -40C to +105C; VOLTAGE: 1.8-3.6V
U7 = LM4040_SOT23: IC VOLT REF SHUNT 3V 0.5% SOT23-3; AGILE_PN: 315-80874; CAD_APPROVED: Yes; HEIGHT: 1.13; MFG_NAME01: TEXAS INSTRUMENTS; ROHS: Yes; VOLTAGE: 3V
U8 = XC6227C_5P: IC VREG LDO  3.3V 0.7A 1.7-6.0V SOT-89-5; 3D_Mechanical_Footprint_File: http://fcl.am.freescale.net/ALLEGRO/step/sot89-5.STEP; AGILE_PN: 315-80827; CAD_APPROVED: Yes; HEIGHT: 1.6mm; MFG_NAME01: TOREX; ROHS: NULL; Temp Range: -40°C to 85°C; VOLTAGE: 1.7V ~ 6.0V
U9 = RCLAMP1654P_NEW: DIODE TVS ARRAY 3 5.5V SLP1616P6; 3D_Mechanical_Footprint_File: http://fcl.am.freescale.net/ALLEGRO/step/slp1616p6.step; AGILE_PN: 480-78843; ASSY_OPT: DNP; CAD_APPROVED: Yes; HEIGHT: 0.65mm; MFG_NAME01: SEMTECH CORP; ROHS: Yes; Rated Voltage: 5.5V; VOLTAGE: 5.5V
Y4 = XTAL: XTAL 16MHZ 8PF AEC-Q200 SMT; 3D_Mechanical_Footprint_File: http://fcl.am.freescale.net/ALLEGRO/step/xtal2_3p3x2p6.STEP; AGILE_PN: 230-78366; CAD_APPROVED: Yes; Frequency Stability: 150ppm; Frequency Tolerance: 50ppm; HEIGHT: 0.95; MFG_NAME01: Kyocera International Inc. Electronic Components; MFG_PN01: CX3225GA16000D0PTVCC; Package Size: 0.126" L x 0.098" W (3.20mm x 2.50mm); ROHS: Yes; Temp Range: -40 to 150 °C
C84-C90 C92-C95 = CAP_NP: CAP CER 0.1UF 16V 10% X7R 0402; 3D_Mechanical_Footprint_File: http://fcl.am.freescale.net/ALLEGRO/step/cc0402_25.STEP; AGILE_PN: 150-75182; CAD_APPROVED: Yes; FPLIST: CC0402_25,CC0402_HD,0402_CC; HEIGHT: 0.635mm; MFG_NAME01: KEMET; MFG_PN01: C0402C104K4RACTU; ROHS: NULL; Rated Voltage: 16V; Temp Range: -55C to +125C; Temp_Range: -55°C to +125°C; Tolerance: 10%; VOLTAGE: 16V
C42 C91 = CAP_NP: CAP CER 10uF 10V 20% X5R 0402_WIDE; AGILE_PN: 150-79255; CAD_APPROVED: Yes; FPLIST: CC0402_25,CC0402_HD,0402_CC; HEIGHT: 0.7; MFG_NAME01: NIC COMPONENTS CORP; MFG_PN01: NMC0402X5R106M10TRPF; ROHS: Yes; Rated Voltage: 10V; Temp Range: -55C to +85C; Tolerance: 20%; VOLTAGE: 10V
C113 = CAP_NP: CAP CER 1000PF 50V 5% C0G 0402; AGILE_PN: 150-76334; ASSY_OPT: DNP; CAD_APPROVED: Yes; FPLIST: CC0402_25,CC0402_HD,0402_CC; HEIGHT: 0.55mm; MFG_NAME01: GUANGDONG VIIYONG ELECTRONIC TECHNOLOGYCO., LTD.VIIYONG; MFG_PN01: V102J0402C0G500NBT; Package Size: 0402; Package Type: 180mm Paper Tape; ROHS: NULL; Rated Voltage: 50V; Temp Range: -55C to +125C; Tolerance: 5%; VOLTAGE: 50V
D12 = DIODE_SCHTKY: DIODE SCH RECT 10V 2A SOD123F; AGILE_PN: 480-78720; CAD_APPROVED: Yes; HEIGHT: 1.2M; MFG_NAME01: NEXPERIA; MFG_PN01: PMEG1020EH,115; ROHS: Yes; Rated Voltage: 10V; VOLTAGE: 10V
D13 D14 = DIODE_TVS: DIODE TVS UNIDIR 3.3VWM 20VC SOD523; AGILE_PN: 480-79814; CAD_APPROVED: Yes; HEIGHT: 0.65MM; MFG_NAME01: NEXPERIA; MFG_PN01: PESD3V3S1UB,115; REQUESTED_COMPLETION_DATE: Not an expedite request; ROHS: Yes
D15 = DIODE_ARRAY_5CH: DIODE TVS UNIDIR 3.3VWM 12VC SOT363; AGILE_PN: 480-79841; CAD_APPROVED: Yes; HEIGHT: 1.1; MFG_NAME01: NEXPERIA; MFG_PN01: PESD3V3L5UY,115; REQUESTED_COMPLETION_DATE: Not an expedite request; ROHS: Yes; Temp Range: -65°C ~ 150°C; Temp_Range: -65°C ~ 150°C
J5 = CONN_HDR_5X2: HDR 2X5 TH 50MIL CTR 222H AU 90L; 3D_Mechanical_Footprint_File: http://fcl.am.freescale.net/ALLEGRO/step/con2x5_50_th_a.STEP; AGILE_PN: 210-82391; CAD_APPROVED: Yes; HEIGHT: 5.65; MFG_NAME01: WURTH ELEKTRONIK EISOS GMBH & CO. KG (ELECTRONIC & ELECTROMEHANICAL COMP); MFG_PN01: 62201021121; ROHS: Yes; Temp Range: -40C to +105C; Temp_Range: -55DegC to +105DegC
JP17 = CONN_HDR_2X1: HDR 1X2 TH 2MM SP 300H AU 102L; AGILE_PN: 210-80456; CAD_APPROVED: Yes; HEIGHT: 7.62; Jumper (Default): OPEN; MFG_NAME01: SAMTEC; ROHS: Yes; SILK: LINK2 TARGET; Temp_Range: -55°C to +105°C
JP18 JP23 JP24 = CONN_HDR_3X1: HDR 1X3 TH 2MM SP 295H AU 102L; AGILE_PN: 210-80201; CAD_APPROVED: Yes; HEIGHT: 7.5; Jumper (Default): 1-2; MFG_NAME01: SAMTEC; MFG_PN01: MTMM-103-06-G-S-236; ROHS: Yes; Temp_Range: -55°C to +125°C
JP25 = CONN_HDR_2X1: HDR 1X2 TH 2MM SP 300H AU 102L; AGILE_PN: 210-80456; CAD_APPROVED: Yes; HEIGHT: 7.62; Jumper (Default): 1-2; MFG_NAME01: SAMTEC; ROHS: Yes; Temp_Range: -55°C to +105°C
R63 R64 R71 = RES: RES MF 10 OHM 1/16W 1% AEC-Q200 0402; AGILE_PN: 470-80978; CAD_APPROVED: Yes; FPLIST: RC0402_25,RC0402_HD,0402_CC; HEIGHT: 0.4; MFG_NAME01: KOA SPEER; MFG_PN01: RK73H1ETTP10R0F; ROHS: Yes; Temp Range: –55 °C to +155 °C; Tolerance: 1%
R66 = RES: RES MF 100K 1/16W 1% 0402; AGILE_PN: 470-76240; ASSY_OPT: DNP; CAD_APPROVED: Yes; FPLIST: RC0402_25,RC0402_HD,0402_CC; HEIGHT: 0.4; MFG_NAME01: VISHAY INTERTECHNOLOGY; MFG_PN01: CRCW0402100KFKEDC; ROHS: Yes; Tolerance: 1%
R68 = RES: RES MF 160K 1/16W 5% AEC-Q200 0402; AGILE_PN: 470-80970; CAD_APPROVED: Yes; HEIGHT: 0.4; MFG_NAME01: KOA SPEER; MFG_PN01: RK73B1ETTP164J; ROHS: Yes; Tolerance: 5%
R70 R74 R77 R80 = RES: RES MF 2.2K 1/16W 1% 0402; 3D_Mechanical_Footprint_File: http://fcl.am.freescale.net/ALLEGRO/step/rc0402_25.STEP; AGILE_PN: 470-78359; CAD_APPROVED: Yes; FPLIST: RC0402_25,RC0402_HD,0402_CC; HEIGHT: 0.4mm; MFG_NAME01: NIC COMPONENTS CORP; MFG_PN01: NRCL04F2201TRF; ROHS: NULL; Temp Range: -55C to +155C; Temp_Range: -55C to +155C; Tolerance: 1%
R75 R79 = RES: RES MF 10K 1/16W 1% 0402; AGILE_PN: 470-80452; CAD_APPROVED: Yes; FPLIST: RC0402_25,RC0402_HD,0402_CC,RC0402_X2; HEIGHT: 0.40; MFG_NAME01: VISHAY; MFG_PN01: CRCW040210K0FKEDC; ROHS: Yes; Tolerance: 1%
SH1-SH6 SH8 SH10-SH15 = RES_SHORT-2: ZERO OHM CUT TRACE 0402 PADS; NO PART TO ORDER; AGILE_PN: 470-76449; CAD_APPROVED: Yes; FPLIST: SH0402,SH0402_CC; HEIGHT: 0.1; ROHS: Yes; SHORTED (DEFAULT): CLOSED
SH20 = RES_SHORT-2: ZERO OHM CUT TRACE 0603 PADS; NO PART TO ORDER; AGILE_PN: 470-80018; CAD_APPROVED: Yes; HEIGHT: 0.1; ROHS: NULL; SHORTED (DEFAULT): CLOSED
SW4 = SW_SPNO_2P_GND6P: SW SPST PB 50MA 12V SMT; AGILE_PN: 510-77720; CAD_APPROVED: Yes; HEIGHT: 2.4; MFG_NAME01: E SWITCH; ROHS: Yes; SILK: BOOT CONFIG
U10 = 74LVC2T45DC_8P: IC TRANSLATING XCVR DUAL BIT/SUPPLY TS 1.2-5.5V VSSOP8; 3D_Mechanical_Footprint_File: http://fcl.am.freescale.net/ALLEGRO/step/ssop8_dcu.STEP; AGILE_PN: 312-81751; CAD_APPROVED: Yes; HEIGHT: 1; MFG_NAME01: NEXPERIA; ROHS: Yes; Temp Range: -40°C to +125°C; VOLTAGE: 1.2 -5.5V
U11 = NX3DV2567GU_XQFN_16P: IC LIN SW 4PDT 1.4-4.3V XQFN16; 3D_Mechanical_Footprint_File: http://fcl.am.freescale.net/ALLEGRO/step/pqfn16_0p4_2p65x1p85.STEP; AGILE_PN: 315-80822; CAD_APPROVED: Yes; HEIGHT: 0.5; MFG_NAME01: NXP SEMICONDUCTOR; MFG_PN01: NX3DV2567GU,115; ROHS: Yes; VOLTAGE: 1.4-4.3V
U12-U14 = 74LVCH1T45_6P: IC XCVR XLATING DUAL 3-STATE 1.2- 5.5V TSSOP6; AGILE_PN: 312-81277; CAD_APPROVED: Yes; HEIGHT: 1.1; MFG_NAME01: NEXPERIA; ROHS: Yes; VOLTAGE: 1.2- 5.5V
U15 = 74AUP1G07GW: IC BUF NON-INV SGL 1.65-5.5V AEC-Q100 TSSOP5; 3D_Mechanical_Footprint_File: http://fcl.am.freescale.net/ALLEGRO/step/sc70-5.STEP; AGILE_PN: 312-82179; CAD_APPROVED: Yes; HEIGHT: 1.1; MFG_NAME01: NEXPERIA; MFG_PN01: 74LVC1G07GW-Q100H; ROHS: Yes; Temp Range: -40 to +125C; VOLTAGE: 1.65-5.5V
J1 J2 = CONN_HDR_8X1: CON 1X8 SKT TH 100MIL SP 335H AU 104L; 3D_Mechanical_Footprint_File: http://fcl.am.freescale.net/ALLEGRO/step/con_1x8_skt_2p54_th_170h.STEP; AGILE_PN: 210-79539; CAD_APPROVED: Yes; HEIGHT: 8.51; MFG_NAME01: SAMTEC; MFG_PN01: SSW-108-01-G-S; ROHS: Yes; Temp Range: -55°C to +125°C
JS5 JS6 = CONN_HDR_2X1: HDR 1X2 TH 2MM SP 217H AU 110L; AGILE_PN: 210-77112; ASSY_OPT: DNP; CAD_APPROVED: Yes; HEIGHT: 5.2; MFG_NAME01: SAMTEC; MFG_PN01: TMM-102-02-G-S; ROHS: Yes; SHORTED (DEFAULT): CLOSED
JS10 JS11 = CONN_HDR_3X1_SHORT: HDR 1X3 TH 100MIL -- NO PART TO ORDER; AGILE_PN: 210-80431; CAD_APPROVED: Yes; HEIGHT: 8.51; MFG_NAME01: NA; MFG_PN01: NO PART TO ORDER1; ROHS: Yes; SHORTED (DEFAULT): CLOSED
Q3 = MOSFET_N: TRAN NMOS 60V 360MA AEC-Q101 TO-236AB; AGILE_PN: 480-79842; CAD_APPROVED: Yes; HEIGHT: 1.1; MFG_NAME01: NEXPERIA; MFG_PN01: BSS138P,215; ROHS: Yes; Temp Range: -65°C ~ 150°C; Temp_Range: -65°C ~ 150°C; VOLTAGE: 60V
R86 = RES: RES MF 10K 1/16W 1% 0402; AGILE_PN: 470-80452; CAD_APPROVED: Yes; FPLIST: RC0402_25,RC0402_HD,0402_CC,RC0402_X2; HEIGHT: 0.40; MFG_NAME01: VISHAY; MFG_PN01: CRCW040210K0FKEDC; ROHS: Yes; TOL: 5%; Tolerance: 1%
U16 = 74AVC4TD245BQ_DHVQFN16: IC DUAL SUPPLY XCVR XLTR 4BIT 0-3.6V DHVQFN16; 3D_Mechanical_Footprint_File: http://fcl.am.freescale.net/ALLEGRO/step/dhvqfn16_0p5_3p6x2p6.STEP; AGILE_PN: 312-81329; CAD_APPROVED: Yes; HEIGHT: 1; MFG_NAME01: NEXPERIA; MFG_PN01: 74AVC4TD245BQ,115; ROHS: Yes

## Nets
3V3_MIKROE: J1.7 SH12.1
5V_MIKROE: J2.7 SH14.2
GND: C42.2 C43.2 C44.2 C45.2 C46.2 C49.2 C50.2 C51.2 C52.2 C53.2 C54.2 C55.2 C56.2 C57.2 C58.2 C59.2 C60.2 C61.2 C62.2 C63.2 C64.2 C65.2 C66.2 C67.2 C68.2 C69.2 C70.2 C71.2 C72.2 C73.2 C74.2 C75.2 C76.2 C77.2 C78.2 C79.2 C80.2 C82.2 C83.2 C84.2 C85.2 C86.2 C87.2 C88.2 C89.2 C90.2 C91.2 C92.2 C93.2 C94.2 C95.2 C113.2 C154.2 C155.1 D13.A D14.A D15.2(A) J1.8 J2.8 J3.A1(GND1) J3.A12(GND2) J3.B1(GND4) J3.B12(GND3) J4.3(A2) J4.5(A3) J4.9(A5) J5.3(A2) J5.5(A3) JP12.1 JP21.1 JP22.1 Q1.2(SOURCE) Q2.2(SOURCE) Q3.2(SOURCE) R25.2 R28.1 R29.1 R38.1 R41.2 R44.2 R53.2 R66.2 R70.2 R71.2 R74.2 R77.2 R79.2 R80.2 R96.2 R104.2 R105.2 R106.2 R112.2 R113.2 R114.1 SW1.1(S1) SW1.G1(GND1) SW1.G2(GND2) SW1.G3(GND3) SW1.G4(GND4) SW2.1(S1) SW2.G1(GND1) SW2.G2(GND2) SW2.G3(GND3) SW2.G4(GND4) SW3.1(S1) SW3.G1(GND1) SW3.G2(GND2) SW3.G3(GND3) SW3.G4(GND4) SW4.G1(GND1) SW4.G2(GND2) SW4.G3(GND3) SW4.G4(GND4) U5.4(GND) U6.18(VREFN) U6.19(VSSA) U6.33(USB1_VSS_2) U6.37(USB1_VSS_1) U6.46(VSS_DCDC1) U6.47(VSS_DCDC2) U6.52(XTAL32K_P) U6.99(USB0_VSS) U6.101(EPAD) U7.2(ANODE) U7.3(ANODE/NC) U8.2(VSS) U9.7(GND) U10.4(GND) U11.6(GND) U12.2(GND) U13.2(GND) U14.2(GND) U15.3(GND) U16.2(DIR1) U16.5(A3) U16.6(A4) U16.8(GND1) U16.17(NC/GND2) Y1.2 Y1.4 ; also on sheet 1 4 5
P5V: SH14.1 ; also on sheet 1 5
VBAT_DCDC/VBAT_PMU: C68.1 C69.1 C72.1 L7.2 U6.49(VBAT_DCDC_1) U6.50(VBAT_DCDC_2) U6.51(VBAT__PMU)
VBUS_USB: J3.A4(VBUS1) J3.A9(VBUS2) J3.B4(VBUS4) J3.B9(VBUS3) L8.1 U9.6(VBUS)
VCC_IF_LINK: C85.1 C88.1 C90.1 C91.1 C93.1 J5.1(A1) JP18.2 R43.1 R68.1 R72.1 R75.1 R76.1 SW4.1(S1) U10.8(VCCB) U12.6(VCCB) U13.6(VCCB) U14.6(VCCB) U15.5(VCC)
VCC_TGMCU: C84.1 C94.1 D12.A JP18.1 R67.2 R86.1 R101.1 SH15.2 U11.14(VCC) U16.1(VCCA) U16.7(DIR4) U16.10(DIR3) U16.15(DIR2)
VDD_DCDC: LED1.A(ANODE) R9.1 ; also on sheet 4 5
VDD_MEM: C44.1 JS1.1 R10.1 R11.1 R19.1 R20.1 U5.8(VCC)
ADC0_A15: C43.1 R8.1 ; also on sheet 4
ADC_IN: R8.2 SH2.2
AN: J1.1 SH2.1
BOOT_CFG: C113.1 SH20.2 SW4.2(S2)
CS: R11.2 R16.2 R21.2 TP11.1(Pin1) U5.1(~{CS})
DBGIF_DETECT: R81.1 U6.78(PIO0_22)
DBGIF_ISP0_CTRL: U6.72(PIO0_14) U15.2(A)
DBGIF_RESET: U6.90(PIO0_19) U14.3(A)
DBGIF_RESET_TXEN: R80.1 U6.71(PIO0_13) U14.5(DIR)
DBGIF_TCK_SWCLK: U6.54(PIO0_0/ACMP0_A) U10.2(1A)
DBGIF_TDI: U6.7(PIO0_1) U10.3(2A)
DBGIF_TDO_SWO: U6.83(PIO0_3/TCK) U12.3(A)
DBGIF_TMS_SWDIO: U6.81(PIO0_2/TRST) U13.3(A)
DBGIF_TMS_SWDIO_TXEN: R74.1 U6.66(PIO0_28/WAKEUP) U13.5(DIR)
DBGIF_VREF: C82.1 R43.2 R44.1 U6.23(PIO0_31/ADC0_3)
EXTAL32K: R31.1 ; also on sheet 4
EXTAL32K_PTD5: C50.1 R31.2 Y2.2
EXTAL_32M: R32.1 Y1.3
EXTAL_RF: R32.2 ; also on sheet 4
FL_USB1_DM: R39.2 U6.35(USB1_DM)
FL_USB1_DP: R40.2 U6.34(USB1_DP)
FL_USB_5V0: C75.1 C76.1 C154.1 L8.2 R37.1 U8.1(CE) U8.4(VIN) ; also on sheet 5
GPO2: JP23.3 ; also on sheet 4
H/RST: R18.2 R20.2 U5.7(~{RESET}/SIO3)
HW_VER_1: R102.1 U6.73(PIO1_28)
HW_VER_2: R104.1 U6.65(PIO1_30/WAKEUP)
HW_VER_3: R105.1 U6.1(PIO1_4)
HW_VER_4: R106.1 U6.31(PIO1_5)
HW_VER_6: JP21.2 Q3.1(GATE) U6.56(PIO0_18/ACMP0_C)
HW_VER_7: JP22.2 U6.27(PIO0) U10.5(DIR)
HW_VER_8: R96.1 U6.55(PIO0_9/ACMP0_B)
I2C1_SCL: R15.1 SH11.1 ; also on sheet 4
I2C1_SDA: JP24.3 R18.1 R21.1 ; also on sheet 4
I2C_SCL: J2.5 SH11.2
I2C_SDA: J2.6 SH13.2
IF_DETECT: D14.C J5.9(A5) R77.1 R81.2
IF_ISPEN: D13.C J5.7(A4) R83.2
IF_TCK_SWDCLK: D15.5(K4) J5.4(B2) R63.2 R79.1 U11.3(2Y1)
IF_TDI: D15.3(K2) J5.8(B4) R64.2
IF_TDO_SWO: D15.4(K3) J5.6(B3) R69.2 U11.11(4Y1)
IF_TMS_SWDIO: D15.6(K5) J5.2(B1) R73.2 R75.2 U11.15(1Y1)
IF_TRGRST_SWDRST: D15.1(K1) J5.10(B5) R78.2 U11.7(3Y1)
L_B4: LED4.C(CATHODE) R22.2
L_G2: LED2.C(CATHODE) R23.1
LED1_B1: JS14.2 Q1.1(GATE) R28.2
LED2_G: Q2.3(DRAIN) R23.2
LED2_G2: Q2.1(GATE) R27.1 R29.2
LED4_B: Q1.3(DRAIN) R22.1
LED_RTS: JS3.2 R24.2
LLWU/NMI_b: J2.2 SH5.2
LPSPI_PCS0: R16.1 SH4.2 ; also on sheet 4
LPSPI_SCK: R12.1 SH6.2 ; also on sheet 4
LPSPI_SIN: R13.1 SH8.2 ; also on sheet 4
LPSPI_SOUT: R14.1 SH10.2 ; also on sheet 4
MCU_LINK_3V3: C51.1 C52.1 C54.1 C55.1 C56.1 C57.1 C58.1 C59.1 C60.1 C61.1 C62.1 C79.1 C80.1 L4.2 U6.15(VDD_1) U6.25(VDD_2) U6.38(USB1_3V3) U6.44(VDD_3) U6.63(VDD_4) U6.69(VDD_5) U6.75(VDD_6) U6.84(VDD_7) U6.95(VDD_8) U6.96(USB0_3V3) U6.100(VDD_9)
MCU_LINK_N_16MHz: C78.1 U6.28(XTAL32M_N) Y4.1
MCU_LINK_P_16MHz: C77.1 U6.29(XTAL32M_P) Y4.2
MCU_LINK_RST: J4.10(B5) U6.32(RESETN)
MCU_LINK_USB_CC1: J3.A5(CC1) R112.1
MCU_LINK_USB_CC2: J3.B5(CC2) R113.1
MCU_LINK_USB_DN: J3.A7(DN1) J3.B7(DN2) R39.1 U9.1(DM)
MCU_LINK_USB_DP: J3.A6(DP1) J3.B6(DP2) R40.1 U9.2(DP)
MCU_LNK_RX: U6.70(PIO0_24) U16.13(B2)
MCU_LNK_TX: U6.79(PIO0_25) U16.14(B1)
MCULINK_VDDA: C63.1 C64.1 L5.2 R33.1 U6.16(VDDA)
MLINK_3V3: C53.1 C83.1 C86.1 C87.1 C89.1 C92.1 C95.1 J4.1(A1) L4.1 L5.1 L7.1 R34.2 R46.1 R47.1 R48.1 R50.1 R102.2 U10.1(VCCA) U12.1(VCCA) U13.1(VCCA) U14.1(VCCA) U16.16(VCCB) ; also on sheet 4
MLINK_FB: C65.1 C66.1 C67.1 L6.2 U6.39(VDD_PMU) U6.45(FB)
MLINK_LX: L6.1 U6.48(LX)
P_LED: JS2.1 LED2.A(ANODE) LED3.A(ANODE) LED4.A(ANODE)
PIO0_5-ISP_EN: J4.7(A4) R51.2
PIO0_5-ISP_EN-LED_SWD_ACT: D7.C(CATHODE) JP12.2 R48.2 R51.1 U6.88(PIO0_5/TDI)
PIO0_10-SWO: J4.6(B3) R46.2 U6.21(PIO0_10/ADC0_1)
PIO0_11-SWDCLK: J4.4(B2) R53.1 U6.13(PIO0_11/ADC0_9)
PIO0_12-SWDIO: J4.2(B1) R47.2 U6.12(PIO0_12/ADC0_10)
PO_LED: LED3.C(CATHODE) R25.1
PTD2/TMP1_CH0: JP23.2 SH3.1
PTD3/I2C1_SDA: JP24.2 SH13.1
PWM: J2.1 SH3.2
RESET: J1.2 SH1.1
RF_GPO_6: JP24.1 ; also on sheet 4
RST_TGTMCU_B: JP25.2 JS3.1 SH1.2 SW1.2(S2) ; also on sheet 4
RST_U11: JP25.1 U11.8(3Z)
SCK: R10.2 R12.2 TP8.1(Pin1) U5.6(SCLK)
SI: R14.2 TP10.1(Pin1) U5.5(SI/SIO0)
SO: R13.2 TP13.1(Pin1) U5.2(SO/SIO1)
SPI_PSC0: J1.3 SH4.1
SPI_SCK: J1.4 SH6.1
SPI_SIN: J1.5 SH8.1
SPI_SOUT: J1.6 SH10.1
SWD_CLK: R66.1 U11.4(2Z) ; also on sheet 4
SWD_DIO: U11.16(1Z) ; also on sheet 4
SWO/BOOT_CFG: SH20.1 U11.12(4Z) ; also on sheet 4
TMP1_CH0: JP23.1 JS14.1 ; also on sheet 4
TMP1_CH5: R27.2 ; also on sheet 4
UART0_RX: JS5.2 JS10.3 ; also on sheet 4
UART0_TX: JS6.2 JS11.3 ; also on sheet 4
UART1_RX: JS10.1 ; also on sheet 1
UART1_TX: JS11.1 ; also on sheet 1
UART_RX: J2.3 JS5.1
UART_TX: J2.4 JS6.1
USB1_VBUS: R37.2 R41.1 U6.36(USB1_VBUS)
V_BRD: C42.1 JS1.2 JS2.2 R17.1 SH12.2 SH15.1 ; also on sheet 1 4 5
VOUT_MLINK: C73.1 C74.1 R34.1 U8.5(VOUT)
VREF_MCULINK: C70.1 C71.1 R33.2 R42.2 U6.17(VREFP) U7.1(CATHODE)
WP: R15.2 R19.2 U5.3(~{W}P/SIO2)
WUU0_P8: C45.1 R9.2 SW2.2(S2) TP9.1(Pin1) ; also on sheet 4
WUU0_P12/NMI_b: C46.1 R17.2 SH5.1 SW3.2(S2) TP12.1(Pin1) ; also on sheet 1 4
XTAL32K: R30.1 ; also on sheet 4
XTAL32K_PTD4: C49.1 R30.2 Y2.1
XTAL_RF: Y1.1 ; also on sheet 4
N22669333: R63.1 U10.7(1B)
N22669352: R64.1 U10.6(2B)
N22669391: R65.1 U11.1(1Y0)
N22669418: JP17.1 R65.2 R67.1 U11.2(S) U11.5(2Y0) U11.9(3Y0)
N22669601: R70.1 U12.5(DIR)
N22669605: R68.2 R69.1 U12.4(B)
N22669808: R72.2 R73.1 U13.4(B)
N22669908: D12.C JP18.3
N22670160: R76.2 R78.1 U14.4(B)
N22670341: R83.1 U15.4(Y)
N22888978: JP17.2 R71.1
N22954457: R84.1 U16.3(A1)
N22954468: R85.1 R101.2 U16.4(A2)
N22954480: Q3.3(DRAIN) R86.2 U16.9(~{OE})
N23559922: R38.2 R42.1 U6.58(PIO1_19/ACMPVREF)
N23802482: D7.A(ANODE) R50.2
N23938720: JS10.2 R84.2
N23938761: JS11.2 R85.2
N24446994: LED1.C(CATHODE) R24.1
N24467715: C155.2 J3.SH1 J3.SH2 J3.SH3 J3.SH4 R114.2

Not connected (* = marked no-connect by the designer): J3 A8(SBU1)* B8(SBU2)*; J4 8(B4)*; U6 2(PIO1_13)* 3(PIO1_24)* 4(PIO1_20)* 5(PIO1_6)* 6(PIO0_7)* 8(PIO0_17)* 9(PIO1_7)* 10(PIO1_9/ADC0_12)* 11(PIO1_0/ADC0)* 14(PIO0_16/ADC0_8)* 20(PIO0_23/ADC0_0)* 22(PIO0_15/ADC0_2)* 24(PIO1_8/ADC0_4)* 26(PIO0_8)* 30(PIO1_21)* 40(PIO1_10)* 41(PIO1_22)* 42(PIO1_23)* 43(PIO1_17)* 53(XTAL32K_N)* 57(PIO1_14/ACMP0_D)* 59(PIO1_1/WAKEUP)* 60(PIO0_26)* 61(PIO1_2)* 62(PIO1_3)* 64(PIO1_18/WAKUP)* 67(PIO1_12)* 68(PIO1_26)* 74(PIO0_20)* 76(PIO0_21)* 77(PIO1_25)* 80(PIO1_29)* 82(PIO1_15)* 85(PIO1_27)* 86(PIO0_4/TMS)* 87(PIO1_16)* 89(PIO0_6/TDO)* 91(PIO1_31)* 92(PIO0_29)* 93(PIO1_11)* 94(PIO0_30)* 97(USB0_DP)* 98(USB0_DM)*; U8 3(NC)*; U9 3(USB_ID)* 4(NC1)* 5(NC2)*; U11 10(NC)* 13(4Y0)*; U15 1(NC)*; U16 11(B4)* 12(B3)*

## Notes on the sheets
sheet 6
- HMI
- LED
- INTERRUPT PUSH BUTTONS
- POWER ON
  INDICATOR
- PTC1
- PTC0
- PTC6
- Note: PCB Shunt on Bottom Side
- PTC7
- USER LED
- 64Mbit (8MB) FLASH
- RESET
- PTB3
- PTB1
- PTB5/LPSPI1_PCS2
- PTB4/LPSPI1_PCS3
- Note: PCB Shunt on Bottom Side
- PTB0
- PTB4/LPSPI1_PCS3
- PTB2
- MCU RST
- Reference Design Area
- CLOCK SECTION
- 32KHz CLOCK CIRCUIT
- 32MHz CLOCK CIRCUIT
sheet 7
- MCU LINK
- 3V3 MCULINK Regulator
- Place C65 & C66
  close to Pin 39
- Place C68, C69 & C72
  close to Pin 49, 50, 51
- MCULINK LEDs
- SWD Activity
- MCULINK SWD
  connector
- PU
- F
- PU
- Open  : Boot from Internal Flash
  Closed: Enable ISP mode (USB1)
- ISP - Onboard Debuger
- HW VER
- ON  / OFF
- HW VER 0
- PWR negotiation
- Low / Open
- MCULink USB
- HW VER 1
- Reserved
- EN  / DIS
- HW VER 2
- SPI/I2C brige
- Open / Low
- USB2.0 Type C
- OB / Pro
- HW VER
- HW VER 3
- MCULink Version
- Low / High
- IC Package
- HW VER 4
- Board Identity
- Low
- EN  / DIS
- HW VER 5
- PWR measurement
- Low / Open
- EN  / DIS
- HW VER 6
- Primary VCOM
- Open / Low
- EN  / DIS
- HW VER 7
- SWD Debug
- Open / Low
- EN  / DIS
- Layout Note:
  ======
  90ohms differential impedance
- HW VER 8
- Secondary VCOM
- Open / Low
sheet 8
- MCU LINK
- Target MCU
- Default  3.3V
- Debug Interface
- SWD_DIO
- PTA0
- SWD_CLK
- PTA1
- DIR#  L: B to A, H: A to B
- MCU RST
- SWO/BOOT_CONF
- PTA4
- S#  L:Z-Y0, H:Z-Y1
- DIR#  L: B to A, H: A to B
- Link2 probe connected to:
- On-board Target
  Off-board Target
- Open (default)
  Shorted
- 10pin JTAG/SWD
- DIR#  L: B to A, H: A to B
- Buffer Power Select:
- On-board Target
  Off-board Target
- 1 - 2 (default)
  2 - 3
- DIR#  L: B to A, H: A to B
- BOOT CONFIG
- ISP - DUT
- PTA4
sheet 9
- MCU LINK
- Voltage Translation
  Buffers
- USB-UART
- Note: Pullup (R101)prevents random output
  on terminal before UART is configured
- Target MCU
- PTC2
- Target Side
- Debugger Side
- TGTMCU_RX
- PTA16
- TGTMCU_TX
- PTC3
- PTA17
- Note: JS10 and JS11 PCB Shunt on Bottom Side
- DIR#  L: B to A
  H: A to B
- MikroBUS Connector
- PTA20
- GPO2
- PTC0
- DTEST_0
- PTA21
- GPO3/GPO7/GPO10
- PTD3
- GPO6
- PTB4
- DTEST_11
- socket boards
- AN
- PWM
- RST
- DTEST_7
- PTB0
- PTD0
- CS
- RST
- INT
- RX
- PTC7
- DTEST_13
- DTEST_9
- PTB2
- SCK
- TX
- LPSPI1
- DTEST_8
- PTB1
- MISO
- SCL
- PTB5
- DTEST_12
- DTEST_10
- PTB3
- MOSI
- SDA
- LPI2C1
- VDD_TARGET
- +5V
- GND
- GND
- CAD Note: PCB Edge Side
- 1. mikroBUS logo positioned above the socket
  2. Pin names corresponding to the routing of the mainboard
  3. A line that encloses the socket on all sides except the top.
  4. A diagonal notch below the right-hand side pinout
       (serves as a guideline for add-on board insertion)
- PTA16
- GPO8
- NOTE:
  TX/RX POKA-YOKE:
  SIN/SOUT POKA-YOKE:
  Place both headers
  with the same orientation
  and provide same airgap
  between TX to RX headers
  terminals in a square fashion.
- Note: PCB Shunt on Bottom Side
- LPUART0
- PTA17
- GPO7
